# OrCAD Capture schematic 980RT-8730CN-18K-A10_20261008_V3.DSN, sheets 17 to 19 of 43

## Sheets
17 P0051_S5_DUT1: size Custom
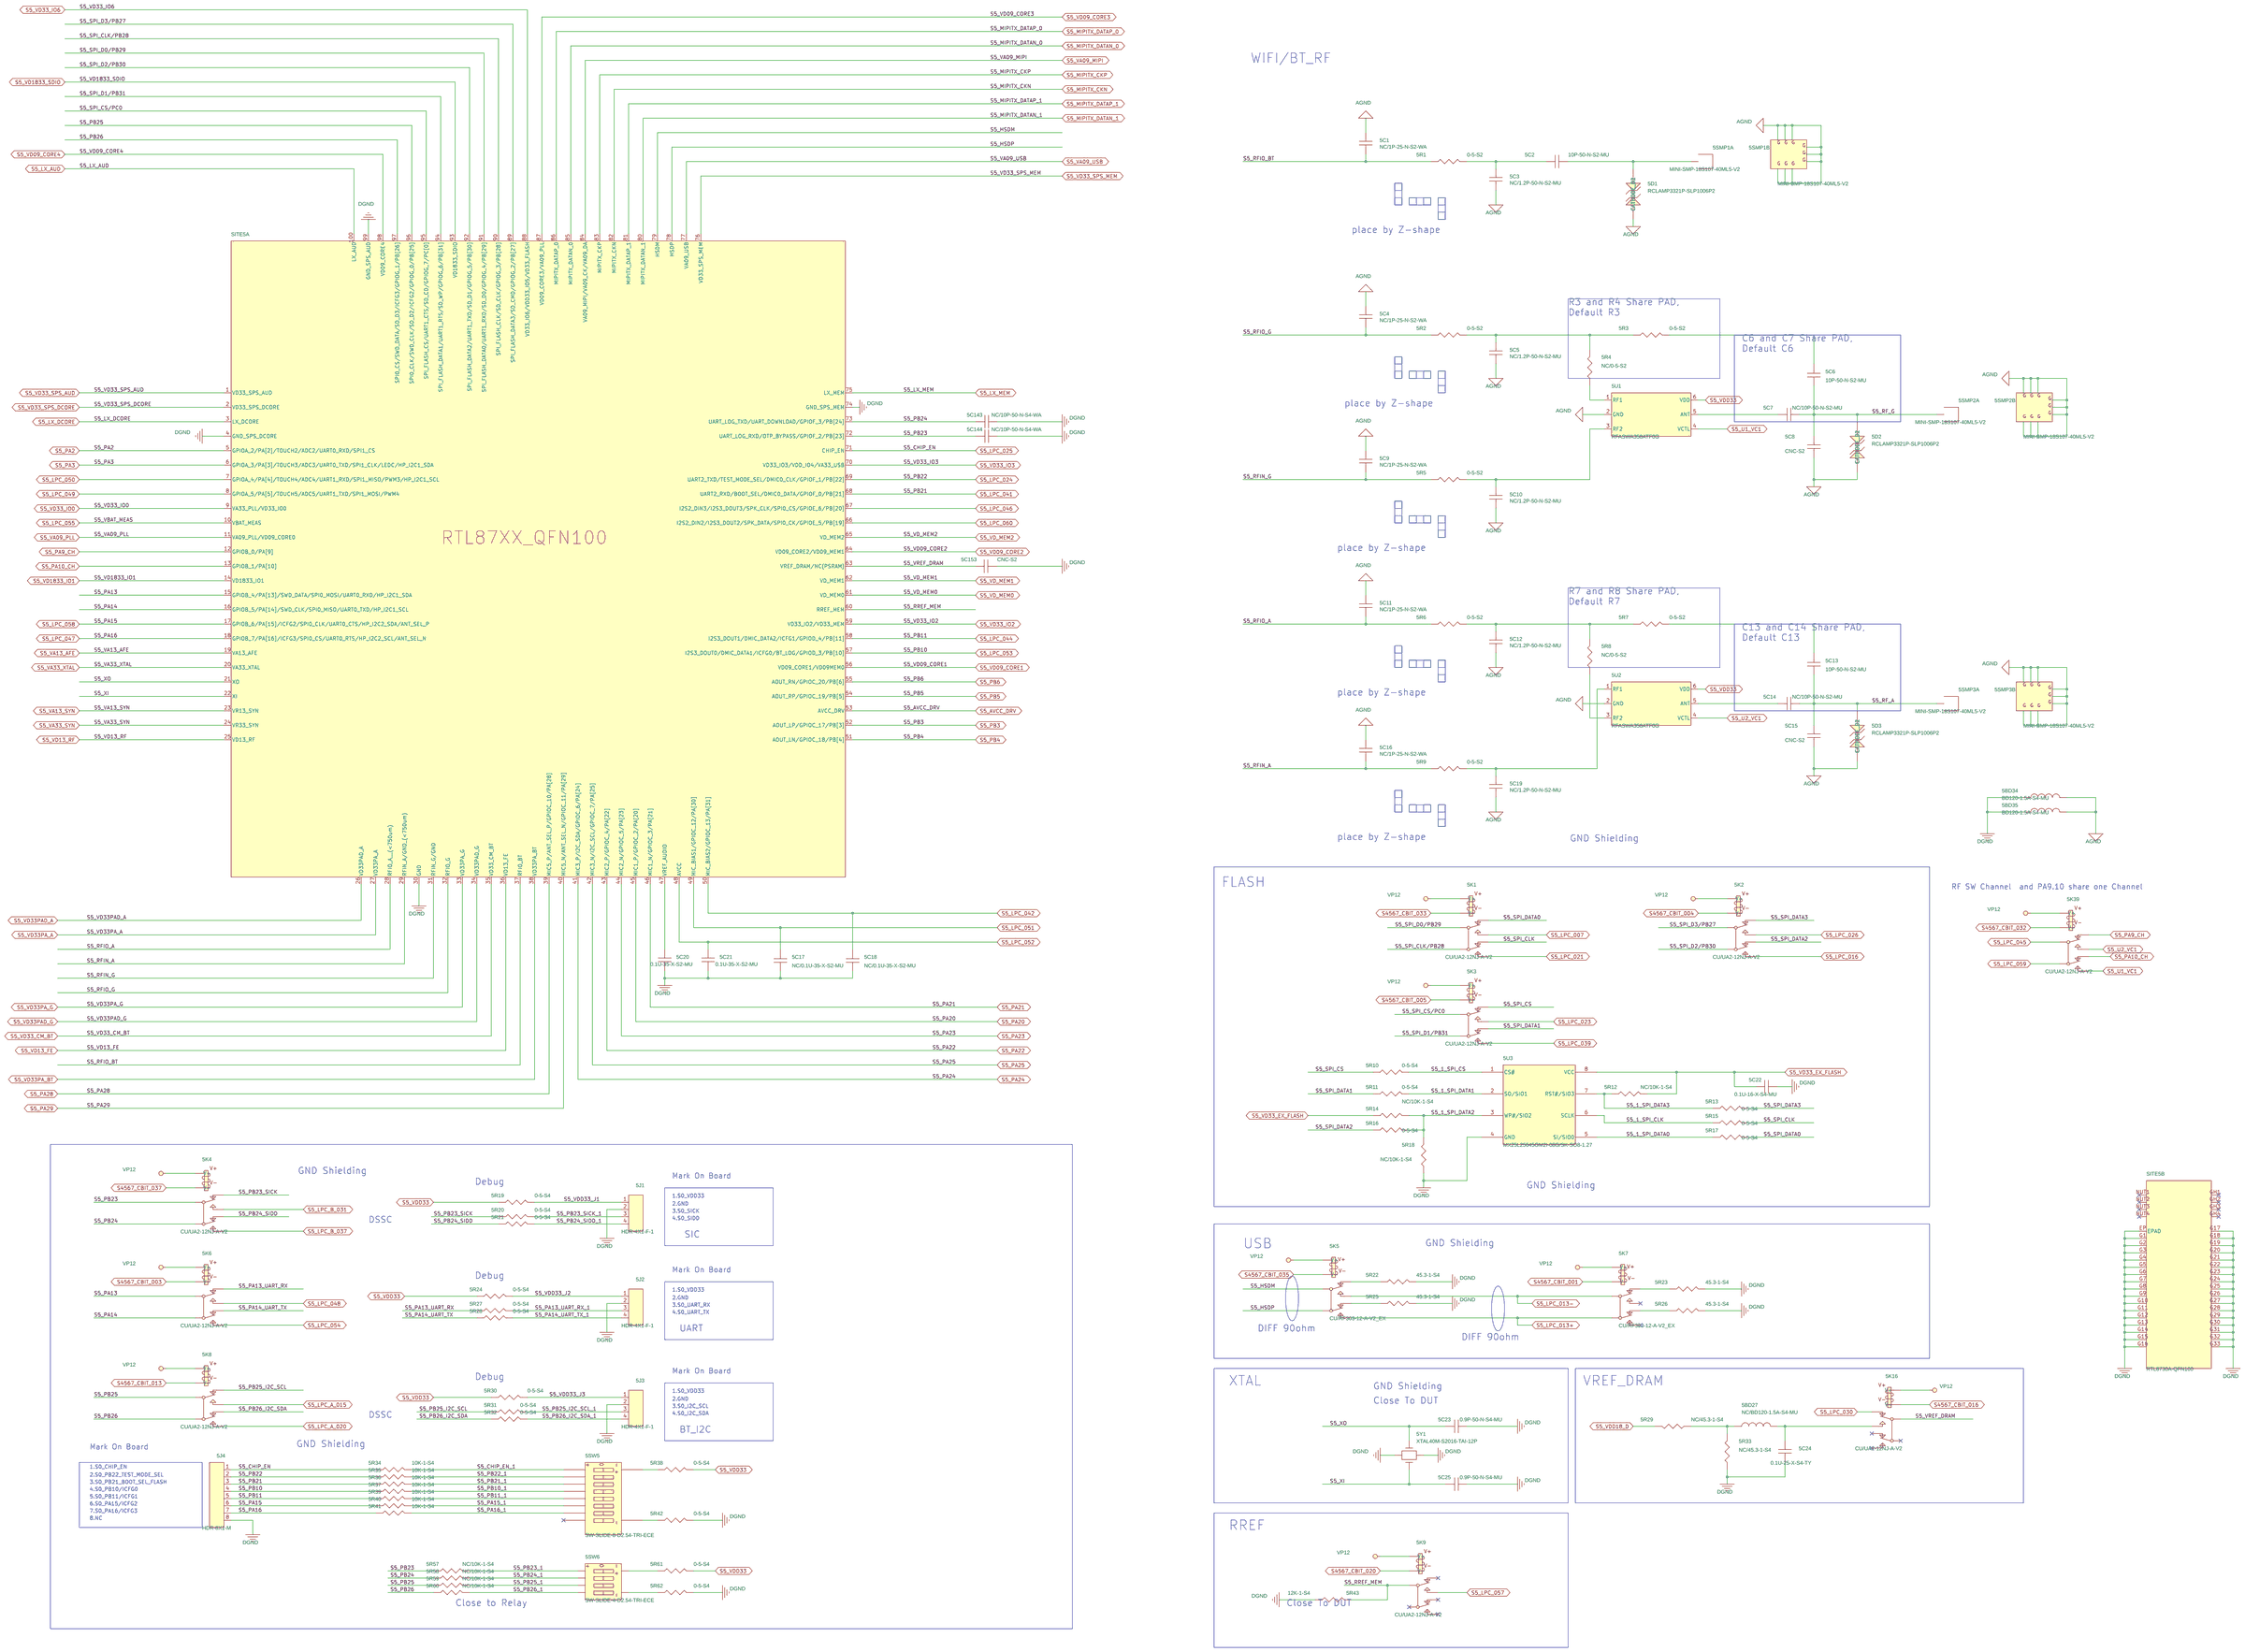
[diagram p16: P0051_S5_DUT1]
18 P0052_S5_Function-test: size A3
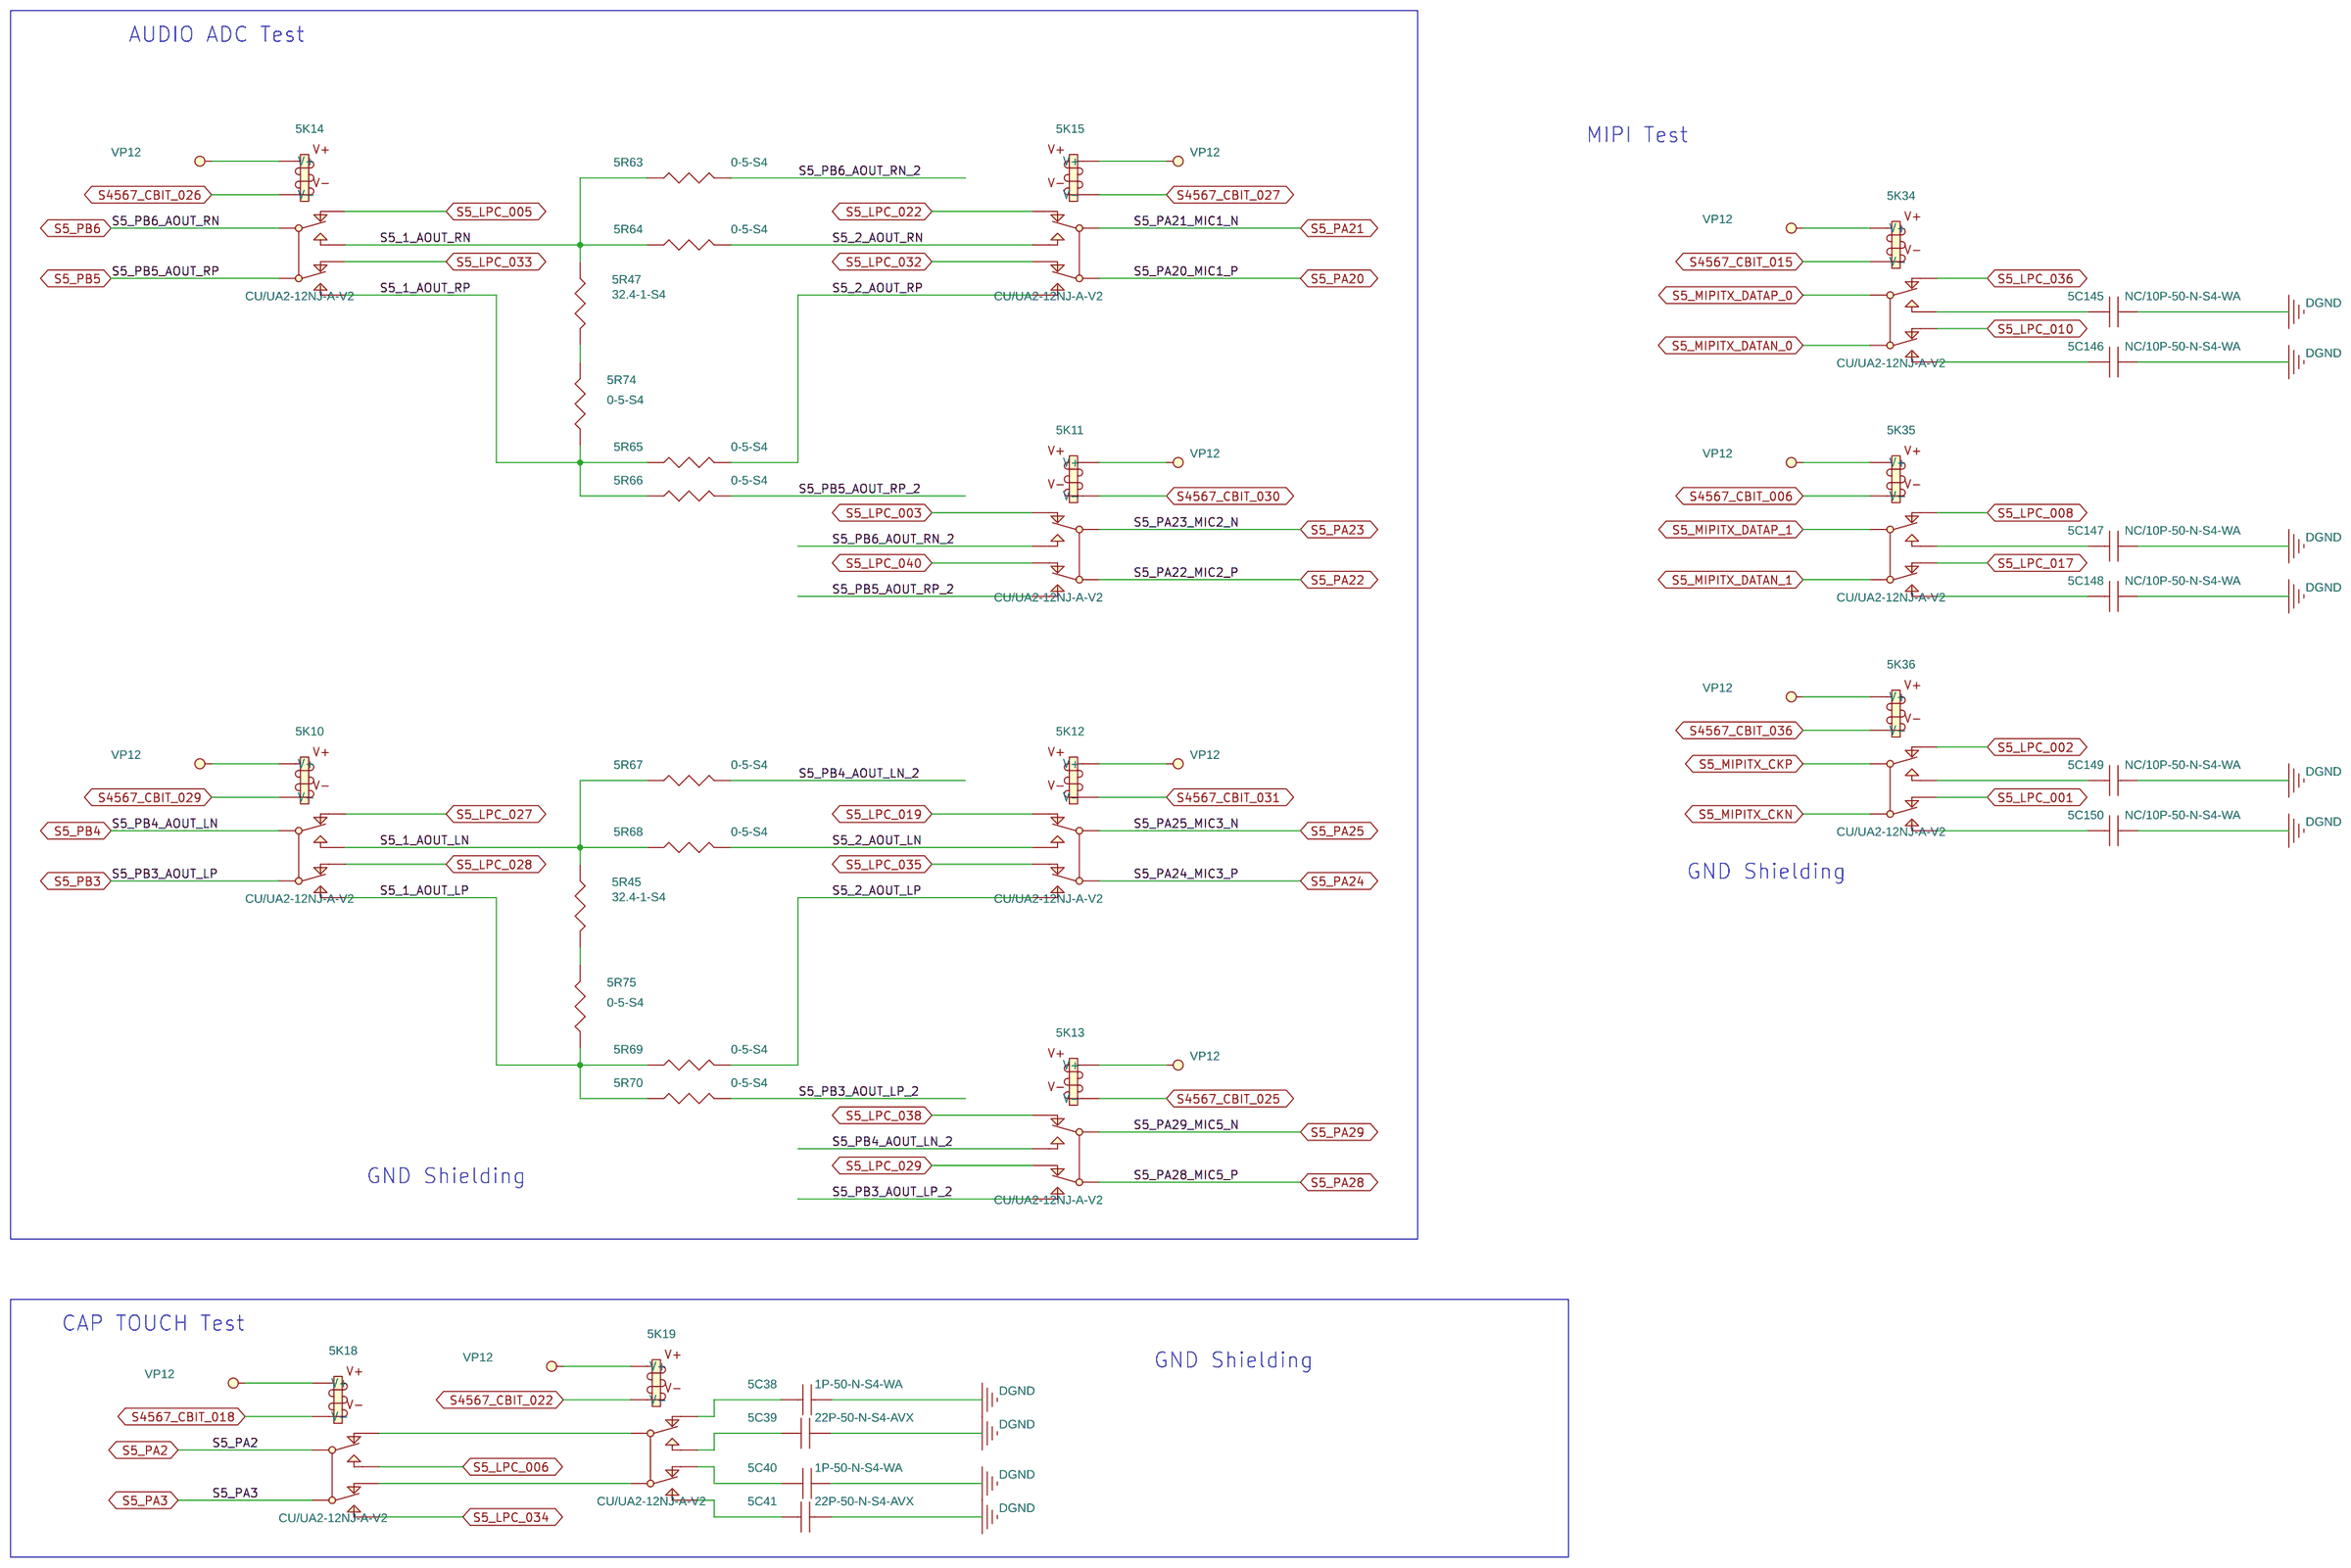
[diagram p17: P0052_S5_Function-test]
19 P0053_S5_Power: size A1
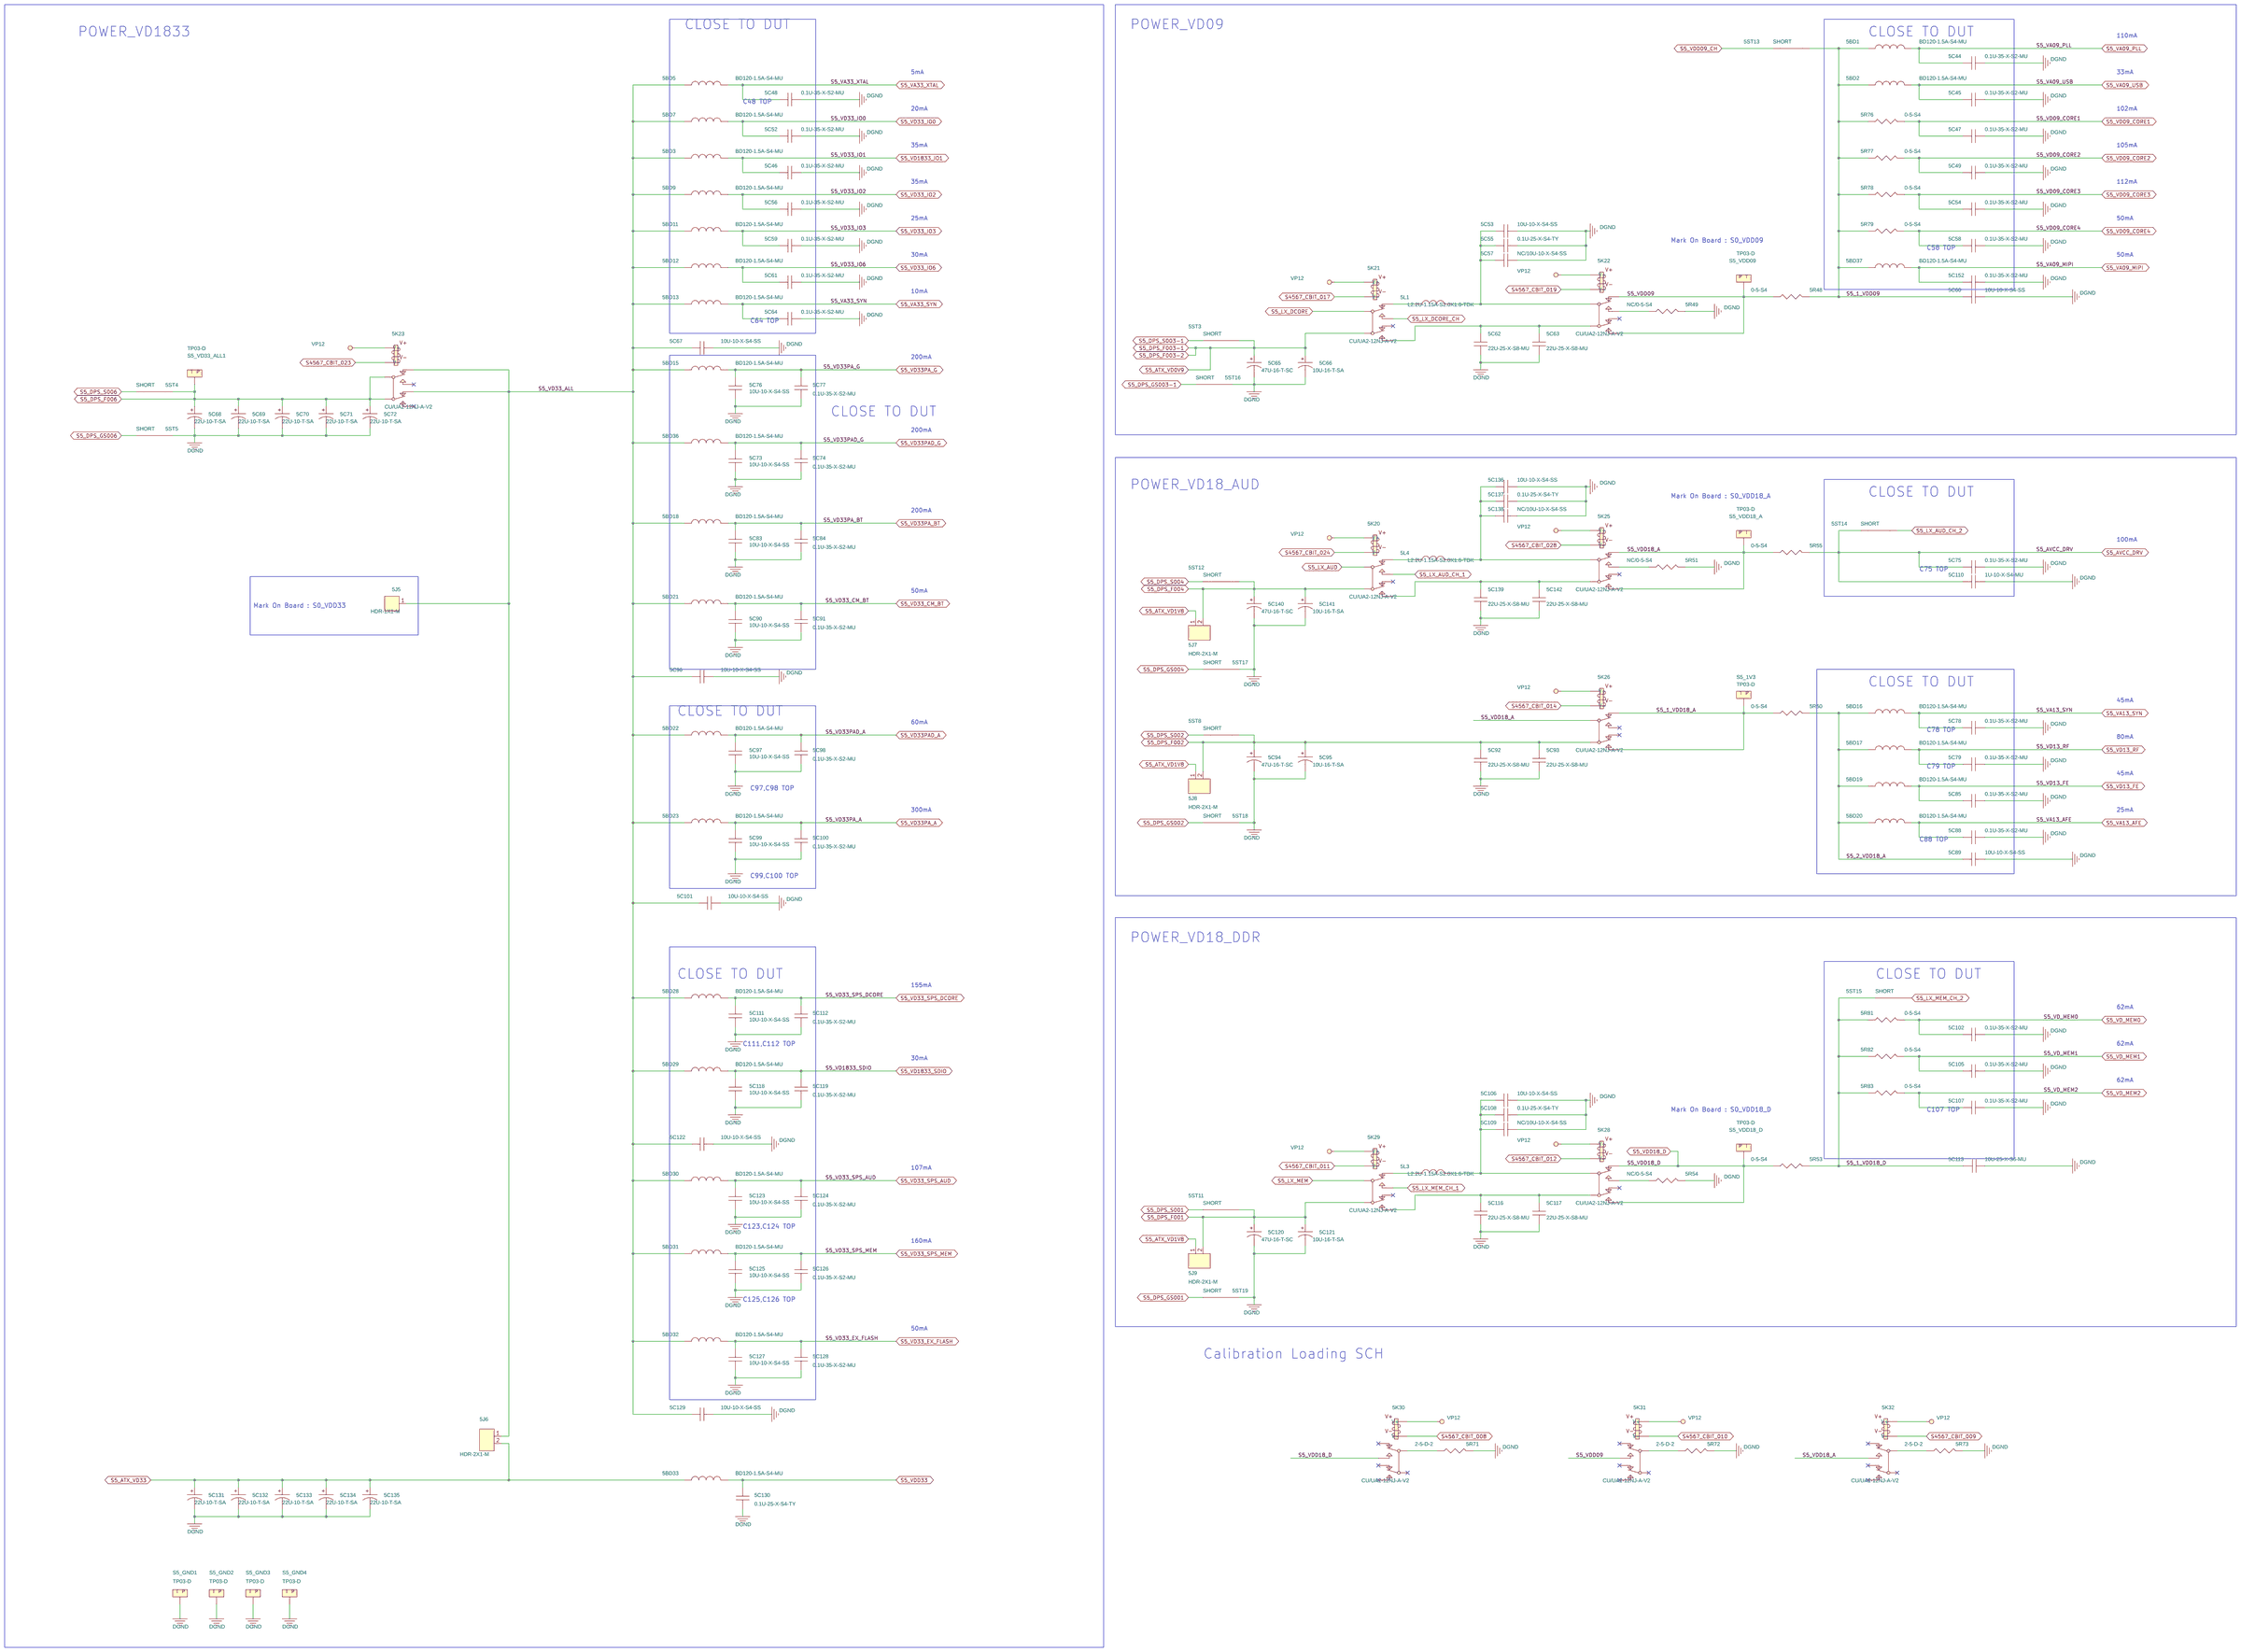
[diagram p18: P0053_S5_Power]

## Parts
sheet P0051_S5_DUT1
5BD27  NC/BD120-1.5A-S4-MU  [FB0402]
5BD34  BD120-1.5A-S4-MU  [FB0402]
5BD35  BD120-1.5A-S4-MU  [FB0402]
5C1  NC/1P-25-N-S2-WA  [C0201]
5C2  10P-50-N-S2-MU  [C0201]
5C3  NC/1.2P-50-N-S2-MU  [C0201]
5C4  NC/1P-25-N-S2-WA  [C0201]
5C5  NC/1.2P-50-N-S2-MU  [C0201]
5C6  10P-50-N-S2-MU  [C0201]
5C7  NC/10P-50-N-S2-MU  [C0201]
5C8  CNC-S2  [C0201]
5C9  NC/1P-25-N-S2-WA  [C0201]
5C10  NC/1.2P-50-N-S2-MU  [C0201]
5C11  NC/1P-25-N-S2-WA  [C0201]
5C12  NC/1.2P-50-N-S2-MU  [C0201]
5C13  10P-50-N-S2-MU  [C0201]
5C14  NC/10P-50-N-S2-MU  [C0201]
5C15  CNC-S2  [C0201]
5C16  NC/1P-25-N-S2-WA  [C0201]
5C17  NC/0.1U-35-X-S2-MU  [C0201]
5C18  NC/0.1U-35-X-S2-MU  [C0201]
5C19  NC/1.2P-50-N-S2-MU  [C0201]
5C20  0.1U-35-X-S2-MU  [C0201]
5C21  0.1U-35-X-S2-MU  [C0201]
5C22  0.1U-16-X-S4-MU  [C0402]
5C23  0.9P-50-N-S4-MU  [C0402]
5C24  0.1U-25-X-S4-TY  [C0402]
5C25  0.9P-50-N-S4-MU  [C0402]
5C143  NC/10P-50-N-S4-WA  [C0402]
5C144  NC/10P-50-N-S4-WA  [C0402]
5C153  CNC-S2  [C0201]
5D1  RCLAMP3321P-SLP1006P2  [DIODE_1X0P6MM]
5D2  RCLAMP3321P-SLP1006P2  [DIODE_1X0P6MM]
5D3  RCLAMP3321P-SLP1006P2  [DIODE_1X0P6MM]
5J1  HDR-4X1-F-1  [CONN_4X1_2P54MM_FL10P5MM]
5J2  HDR-4X1-F-1  [CONN_4X1_2P54MM_FL10P5MM]
5J3  HDR-4X1-F-1  [CONN_4X1_2P54MM_FL10P5MM]
5J4  HDR-8X1-M  [JP_8P_100]
5K1  CU/UA2-12NJ-A-V2  [RL_NECUA2_12V_V2]
5K2  CU/UA2-12NJ-A-V2  [RL_NECUA2_12V_V2]
5K3  CU/UA2-12NJ-A-V2  [RL_NECUA2_12V_V2]
5K4  CU/UA2-12NJ-A-V2  [RL_NECUA2_12V_V2]
5K5  CU/RF303-12-A-V2_EX  [RL_RF303_12V_V2]
5K6  CU/UA2-12NJ-A-V2  [RL_NECUA2_12V_V2]
5K7  CU/RF303-12-A-V2_EX  [RL_RF303_12V_V2]
5K8  CU/UA2-12NJ-A-V2  [RL_NECUA2_12V_V2]
5K9  CU/UA2-12NJ-A-V2  [RL_NECUA2_12V_V2]
5K16  CU/UA2-12NJ-A-V2  [RL_NECUA2_12V_V2]
5K39  CU/UA2-12NJ-A-V2  [RL_NECUA2_12V_V2]
5R1  0-5-S2  [R0201]
5R2  0-5-S2  [R0201]
5R3  0-5-S2  [R0201]
5R4  NC/0-5-S2  [R0201]
5R5  0-5-S2  [R0201]
5R6  0-5-S2  [R0201]
5R7  0-5-S2  [R0201]
5R8  NC/0-5-S2  [R0201]
5R9  0-5-S2  [R0201]
5R10  0-5-S4  [R0402]
5R11  0-5-S4  [R0402]
5R12  NC/10K-1-S4  [R0402]
5R13  0-5-S4  [R0402]
5R14  NC/10K-1-S4  [R0402]
5R15  0-5-S4  [R0402]
5R16  0-5-S4  [R0402]
5R17  0-5-S4  [R0402]
5R18  NC/10K-1-S4  [R0402]
5R19  0-5-S4  [R0402]
5R20  0-5-S4  [R0402]
5R21  0-5-S4  [R0402]
5R22  45.3-1-S4  [R0402]
5R23  45.3-1-S4  [R0402]
5R24  0-5-S4  [R0402]
5R25  45.3-1-S4  [R0402]
5R26  45.3-1-S4  [R0402]
5R27  0-5-S4  [R0402]
5R28  0-5-S4  [R0402]
5R29  NC/45.3-1-S4  [R0402]
5R30  0-5-S4  [R0402]
5R31  0-5-S4  [R0402]
5R32  0-5-S4  [R0402]
5R33  NC/45.3-1-S4  [R0402]
5R34  10K-1-S4  [R0402]
5R35  10K-1-S4  [R0402]
5R36  10K-1-S4  [R0402]
5R37  10K-1-S4  [R0402]
5R38  0-5-S4  [R0402]
5R39  10K-1-S4  [R0402]
5R40  10K-1-S4  [R0402]
5R41  10K-1-S4  [R0402]
5R42  0-5-S4  [R0402]
5R43  12K-1-S4  [R0402]
5R57  NC/10K-1-S4  [R0402]
5R58  NC/10K-1-S4  [R0402]
5R59  NC/10K-1-S4  [R0402]
5R60  NC/10K-1-S4  [R0402]
5R61  0-5-S4  [R0402]
5R62  0-5-S4  [R0402]
5SMP1  MINI-SMP-18S107-40ML5-V2  [CONN_SMP_18S107]  (sections A,B)
5SMP2  MINI-SMP-18S107-40ML5-V2  [CONN_SMP_18S107]  (sections A,B)
5SMP3  MINI-SMP-18S107-40ML5-V2  [CONN_SMP_18S107]  (sections A,B)
5SW5  SW-SLIDE-8-D2.54-TRI-ECE  [SW_DIPX8P_2P54_MM_V2]
5SW6  SW-SLIDE-4-D2.54-TRI-ECE  [SW_DIPX4P_2P54MM_ETD]
5U1  RFASWA358ATF0G  [RF_SW_GW2159_6P]
5U2  RFASWA358ATF0G  [RF_SW_GW2159_6P]
5U3  MX25L25645GM2I-08G/SK-SO8-1.27  [SK_SO8_1P27MM_LOTES]
5Y1  XTAL40M-S2016-TAI-12P  [XTAL_2X1P6MM_4P_0P8MM]
SITE5  RTL8730A-QFN100  [SK_QFN100P_0P35MM_MJC_L8730A]  (sections A,B)
sheet P0052_S5_Function-test
5C38  1P-50-N-S4-WA  [C0402]
5C39  22P-50-N-S4-AVX  [C0402]
5C40  1P-50-N-S4-WA  [C0402]
5C41  22P-50-N-S4-AVX  [C0402]
5C145  NC/10P-50-N-S4-WA  [C0402]
5C146  NC/10P-50-N-S4-WA  [C0402]
5C147  NC/10P-50-N-S4-WA  [C0402]
5C148  NC/10P-50-N-S4-WA  [C0402]
5C149  NC/10P-50-N-S4-WA  [C0402]
5C150  NC/10P-50-N-S4-WA  [C0402]
5K10  CU/UA2-12NJ-A-V2  [RL_NECUA2_12V_V2]
5K11  CU/UA2-12NJ-A-V2  [RL_NECUA2_12V_V2]
5K12  CU/UA2-12NJ-A-V2  [RL_NECUA2_12V_V2]
5K13  CU/UA2-12NJ-A-V2  [RL_NECUA2_12V_V2]
5K14  CU/UA2-12NJ-A-V2  [RL_NECUA2_12V_V2]
5K15  CU/UA2-12NJ-A-V2  [RL_NECUA2_12V_V2]
5K18  CU/UA2-12NJ-A-V2  [RL_NECUA2_12V_V2]
5K19  CU/UA2-12NJ-A-V2  [RL_NECUA2_12V_V2]
5K34  CU/UA2-12NJ-A-V2  [RL_NECUA2_12V_V2]
5K35  CU/UA2-12NJ-A-V2  [RL_NECUA2_12V_V2]
5K36  CU/UA2-12NJ-A-V2  [RL_NECUA2_12V_V2]
5R45  32.4-1-S4  [R0402]
5R47  32.4-1-S4  [R0402]
5R63  0-5-S4  [R0402]
5R64  0-5-S4  [R0402]
5R65  0-5-S4  [R0402]
5R66  0-5-S4  [R0402]
5R67  0-5-S4  [R0402]
5R68  0-5-S4  [R0402]
5R69  0-5-S4  [R0402]
5R70  0-5-S4  [R0402]
5R74  0-5-S4  [R0402]
5R75  0-5-S4  [R0402]
sheet P0053_S5_Power
5BD1  BD120-1.5A-S4-MU  [FB0402]
5BD2  BD120-1.5A-S4-MU  [FB0402]
5BD3  BD120-1.5A-S4-MU  [FB0402]
5BD5  BD120-1.5A-S4-MU  [FB0402]
5BD7  BD120-1.5A-S4-MU  [FB0402]
5BD9  BD120-1.5A-S4-MU  [FB0402]
5BD11  BD120-1.5A-S4-MU  [FB0402]
5BD12  BD120-1.5A-S4-MU  [FB0402]
5BD13  BD120-1.5A-S4-MU  [FB0402]
5BD15  BD120-1.5A-S4-MU  [FB0402]
5BD16  BD120-1.5A-S4-MU  [FB0402]
5BD17  BD120-1.5A-S4-MU  [FB0402]
5BD18  BD120-1.5A-S4-MU  [FB0402]
5BD19  BD120-1.5A-S4-MU  [FB0402]
5BD20  BD120-1.5A-S4-MU  [FB0402]
5BD21  BD120-1.5A-S4-MU  [FB0402]
5BD22  BD120-1.5A-S4-MU  [FB0402]
5BD23  BD120-1.5A-S4-MU  [FB0402]
5BD28  BD120-1.5A-S4-MU  [FB0402]
5BD29  BD120-1.5A-S4-MU  [FB0402]
5BD30  BD120-1.5A-S4-MU  [FB0402]
5BD31  BD120-1.5A-S4-MU  [FB0402]
5BD32  BD120-1.5A-S4-MU  [FB0402]
5BD33  BD120-1.5A-S4-MU  [FB0402]
5BD36  BD120-1.5A-S4-MU  [FB0402]
5BD37  BD120-1.5A-S4-MU  [FB0402]
5C44  0.1U-35-X-S2-MU  [C0201]
5C45  0.1U-35-X-S2-MU  [C0201]
5C46  0.1U-35-X-S2-MU  [C0201]
5C47  0.1U-35-X-S2-MU  [C0201]
5C48  0.1U-35-X-S2-MU  [C0201]
5C49  0.1U-35-X-S2-MU  [C0201]
5C52  0.1U-35-X-S2-MU  [C0201]
5C53  10U-10-X-S4-SS  [C0402]
5C54  0.1U-35-X-S2-MU  [C0201]
5C55  0.1U-25-X-S4-TY  [C0402]
5C56  0.1U-35-X-S2-MU  [C0201]
5C57  NC/10U-10-X-S4-SS  [C0402]
5C58  0.1U-35-X-S2-MU  [C0201]
5C59  0.1U-35-X-S2-MU  [C0201]
5C60  10U-10-X-S4-SS  [C0402]
5C61  0.1U-35-X-S2-MU  [C0201]
5C62  22U-25-X-S8-MU  [C0805]
5C63  22U-25-X-S8-MU  [C0805]
5C64  0.1U-35-X-S2-MU  [C0201]
5C65  47U-16-T-SC  [CODE_C]
5C66  10U-16-T-SA  [CODE_A]
5C67  10U-10-X-S4-SS  [C0402]
5C68  22U-10-T-SA  [CODE_A]
5C69  22U-10-T-SA  [CODE_A]
5C70  22U-10-T-SA  [CODE_A]
5C71  22U-10-T-SA  [CODE_A]
5C72  22U-10-T-SA  [CODE_A]
5C73  10U-10-X-S4-SS  [C0402]
5C74  0.1U-35-X-S2-MU  [C0201]
5C75  0.1U-35-X-S2-MU  [C0201]
5C76  10U-10-X-S4-SS  [C0402]
5C77  0.1U-35-X-S2-MU  [C0201]
5C78  0.1U-35-X-S2-MU  [C0201]
5C79  0.1U-35-X-S2-MU  [C0201]
5C83  10U-10-X-S4-SS  [C0402]
5C84  0.1U-35-X-S2-MU  [C0201]
5C85  0.1U-35-X-S2-MU  [C0201]
5C88  0.1U-35-X-S2-MU  [C0201]
5C89  10U-10-X-S4-SS  [C0402]
5C90  10U-10-X-S4-SS  [C0402]
5C91  0.1U-35-X-S2-MU  [C0201]
5C92  22U-25-X-S8-MU  [C0805]
5C93  22U-25-X-S8-MU  [C0805]
5C94  47U-16-T-SC  [CODE_C]
5C95  10U-16-T-SA  [CODE_A]
5C96  10U-10-X-S4-SS  [C0402]
5C97  10U-10-X-S4-SS  [C0402]
5C98  0.1U-35-X-S2-MU  [C0201]
5C99  10U-10-X-S4-SS  [C0402]
5C100  0.1U-35-X-S2-MU  [C0201]
5C101  10U-10-X-S4-SS  [C0402]
5C102  0.1U-35-X-S2-MU  [C0201]
5C105  0.1U-35-X-S2-MU  [C0201]
5C106  10U-10-X-S4-SS  [C0402]
5C107  0.1U-35-X-S2-MU  [C0201]
5C108  0.1U-25-X-S4-TY  [C0402]
5C109  NC/10U-10-X-S4-SS  [C0402]
5C110  1U-10-X-S4-MU  [C0402]
5C111  10U-10-X-S4-SS  [C0402]
5C112  0.1U-35-X-S2-MU  [C0201]
5C113  10U-25-X-S6-MU  [C0603]
5C116  22U-25-X-S8-MU  [C0805]
5C117  22U-25-X-S8-MU  [C0805]
5C118  10U-10-X-S4-SS  [C0402]
5C119  0.1U-35-X-S2-MU  [C0201]
5C120  47U-16-T-SC  [CODE_C]
5C121  10U-16-T-SA  [CODE_A]
5C122  10U-10-X-S4-SS  [C0402]
5C123  10U-10-X-S4-SS  [C0402]
5C124  0.1U-35-X-S2-MU  [C0201]
5C125  10U-10-X-S4-SS  [C0402]
5C126  0.1U-35-X-S2-MU  [C0201]
5C127  10U-10-X-S4-SS  [C0402]
5C128  0.1U-35-X-S2-MU  [C0201]
5C129  10U-10-X-S4-SS  [C0402]
5C130  0.1U-25-X-S4-TY  [C0402]
5C131  22U-10-T-SA  [CODE_A]
5C132  22U-10-T-SA  [CODE_A]
5C133  22U-10-T-SA  [CODE_A]
5C134  22U-10-T-SA  [CODE_A]
5C135  22U-10-T-SA  [CODE_A]
5C136  10U-10-X-S4-SS  [C0402]
5C137  0.1U-25-X-S4-TY  [C0402]
5C138  NC/10U-10-X-S4-SS  [C0402]
5C139  22U-25-X-S8-MU  [C0805]
5C140  47U-16-T-SC  [CODE_C]
5C141  10U-16-T-SA  [CODE_A]
5C142  22U-25-X-S8-MU  [C0805]
5C152  0.1U-35-X-S2-MU  [C0201]
5J5  HDR-1X1-M  [JP_1P_RD070_040]
5J6  HDR-2X1-M  [JP_2P_100]
5J7  HDR-2X1-M  [JP_2P_100]
5J8  HDR-2X1-M  [JP_2P_100]
5J9  HDR-2X1-M  [JP_2P_100]
5K20  CU/UA2-12NJ-A-V2  [RL_NECUA2_12V_V2]
5K21  CU/UA2-12NJ-A-V2  [RL_NECUA2_12V_V2]
5K22  CU/UA2-12NJ-A-V2  [RL_NECUA2_12V_V2]
5K23  CU/UA2-12NJ-A-V2  [RL_NECUA2_12V_V2]
5K25  CU/UA2-12NJ-A-V2  [RL_NECUA2_12V_V2]
5K26  CU/UA2-12NJ-A-V2  [RL_NECUA2_12V_V2]
5K28  CU/UA2-12NJ-A-V2  [RL_NECUA2_12V_V2]
5K29  CU/UA2-12NJ-A-V2  [RL_NECUA2_12V_V2]
5K30  CU/UA2-12NJ-A-V2  [RL_NECUA2_12V_V2]
5K31  CU/UA2-12NJ-A-V2  [RL_NECUA2_12V_V2]
5K32  CU/UA2-12NJ-A-V2  [RL_NECUA2_12V_V2]
5L1  L2.2U-1.15A-S2.0X1.6-TDK  [IND_VL252012E]
5L3  L2.2U-1.15A-S2.0X1.6-TDK  [IND_VL252012E]
5L4  L2.2U-1.15A-S2.0X1.6-TDK  [IND_VL252012E]
5R48  0-5-S4  [R0402]
5R49  NC/0-5-S4  [R0402]
5R50  0-5-S4  [R0402]
5R51  NC/0-5-S4  [R0402]
5R53  0-5-S4  [R0402]
5R54  NC/0-5-S4  [R0402]
5R55  0-5-S4  [R0402]
5R71  2-5-D-2  [RC02W_27MM]
5R72  2-5-D-2  [RC02W_27MM]
5R73  2-5-D-2  [RC02W_27MM]
5R76  0-5-S4  [R0402]
5R77  0-5-S4  [R0402]
5R78  0-5-S4  [R0402]
5R79  0-5-S4  [R0402]
5R81  0-5-S4  [R0402]
5R82  0-5-S4  [R0402]
5R83  0-5-S4  [R0402]
5ST3  SHORT  [DEFAULT_SHORT_SMALL]
5ST4  SHORT  [DEFAULT_SHORT_SMALL]
5ST5  SHORT  [DEFAULT_SHORT_SMALL]
5ST8  SHORT  [DEFAULT_SHORT_SMALL]
5ST11  SHORT  [DEFAULT_SHORT_SMALL]
5ST12  SHORT  [DEFAULT_SHORT_SMALL]
5ST13  SHORT  [DEFAULT_SHORT_SMALL]
5ST14  SHORT  [DEFAULT_SHORT_SMALL]
5ST15  SHORT  [DEFAULT_SHORT_SMALL]
5ST16  SHORT  [DEFAULT_SHORT_SMALL]
5ST17  SHORT  [DEFAULT_SHORT_SMALL]
5ST18  SHORT  [DEFAULT_SHORT_SMALL]
5ST19  SHORT  [DEFAULT_SHORT_SMALL]
S5_1V3  TP03-D  [TP_060_040]
S5_GND1  TP03-D  [TP_060_040]
S5_GND2  TP03-D  [TP_060_040]
S5_GND3  TP03-D  [TP_060_040]
S5_GND4  TP03-D  [TP_060_040]
S5_VD33_ALL1  TP03-D  [TP_060_040]
S5_VDD09  TP03-D  [TP_060_040]
S5_VDD18_A  TP03-D  [TP_060_040]
S5_VDD18_D  TP03-D  [TP_060_040]

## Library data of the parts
5BD27 = BD120-1.5A-S4-MU: KAIROSNAME: BD27
5BD34 = BD120-1.5A-S4-MU: KAIROSNAME: BD34
5BD35 = BD120-1.5A-S4-MU: KAIROSNAME: BD35
5C1 5C4 5C9 5C11 5C16 = 1P-25-N-S2-WA
5C2 5C6 5C7 5C13 5C14 = 10P-50-N-S2-MU
5C3 5C5 5C10 5C12 5C19 = 1.2P-50-N-S2-MU
5C8 5C15 = CNC-S4
5C17 5C18 5C46 = 0.1U-35-X-S2-MU: KAIROSNAME: C46
5C20 5C21 5C98 = 0.1U-35-X-S2-MU: KAIROSNAME: C98
5C22 = 0.1U-16-X-S4: KAIROSNAME: C22
5C23 = 10P-50-N-S4-MU-1: KAIROSNAME: C23
5C24 = 0.1U-25-X-S4-TY: KAIROSNAME: C24
5C25 = 10P-50-N-S4-MU-1: KAIROSNAME: C25
5C143-5C150 = 10P-50-N-S4-WA
5C48 5C153 = 0.1U-35-X-S2-MU: KAIROSNAME: C48
5D1 = RCLAMP3321P-SLP1006P2: KAIROSNAME: D1
5D2 = RCLAMP3321P-SLP1006P2: KAIROSNAME: D2
5D3 = RCLAMP3321P-SLP1006P2: KAIROSNAME: D3
5J1-5J3 = HDR-4X1-F-1
5J4 = HDR-8X1-M: KAIROSNAME: J4
5K1 5K39 = CU_UA2-12NJ-A-V2: KAIROSNAME: K1
5K2 5K16 = CU_UA2-12NJ-A-V2: KAIROSNAME: K2
5K3 = CU_UA2-12NJ-A-V2: KAIROSNAME: K3
5K4 = CU_UA2-12NJ-A-V2: KAIROSNAME: K4
5K5 = CU_RF303-12-A-V2_EX: KAIROSNAME: K5
5K6 = CU_UA2-12NJ-A-V2: KAIROSNAME: K6
5K7 = CU_RF303-12-A-V2_EX: KAIROSNAME: K7
5K8 = CU_UA2-12NJ-A-V2: KAIROSNAME: K8
5K9 = CU_UA2-12NJ-A-V2: KAIROSNAME: K9
5R1-5R9 = 0-5-S2
5R10 = 0-5-S4: KAIROSNAME: R10
5R11 = 0-5-S4: KAIROSNAME: R11
5R12 = 10K-1-S4: KAIROSNAME: R12
5R13 = 0-5-S4: KAIROSNAME: R13
5R14 = 10K-1-S4: KAIROSNAME: R14
5R15 = 0-5-S4: KAIROSNAME: R15
5R16 = 0-5-S4: KAIROSNAME: R16
5R17 = 0-5-S4: KAIROSNAME: R17
5R18 = 10K-1-S4: KAIROSNAME: R18
5R19 = 0-5-S4: KAIROSNAME: R19
5R20 = 0-5-S4: KAIROSNAME: R20
5R21 = 0-5-S4: KAIROSNAME: R21
5R22 = 45.3-1-S4: KAIROSNAME: R22
5R23 = 45.3-1-S4: KAIROSNAME: R23
5R24 = 0-5-S4: KAIROSNAME: R24
5R25 = 45.3-1-S4: KAIROSNAME: R25
5R26 = 45.3-1-S4: KAIROSNAME: R26
5R27 = 0-5-S4: KAIROSNAME: R27
5R28 = 0-5-S4: KAIROSNAME: R28
5R29 = 45.3-1-S4: KAIROSNAME: R29
5R30 = 0-5-S4: KAIROSNAME: R30
5R31 = 0-5-S4: KAIROSNAME: R31
5R32 = 0-5-S4: KAIROSNAME: R32
5R33 = 45.3-1-S4: KAIROSNAME: R33
5R34 = 10K-1-S4: KAIROSNAME: R34
5R35 = 10K-1-S4: KAIROSNAME: R35
5R36 = 10K-1-S4: KAIROSNAME: R36
5R37 = 10K-1-S4: KAIROSNAME: R37
5R38 = 0-5-S4: KAIROSNAME: R38
5R39 = 10K-1-S4: KAIROSNAME: R39
5R40 = 10K-1-S4: KAIROSNAME: R40
5R41 = 10K-1-S4: KAIROSNAME: R41
5R42 = 0-5-S4: KAIROSNAME: R42
5R43 = 12K-1-S4: KAIROSNAME: R43
5R57 = 10K-1-S4: KAIROSNAME: R57
5R58 = 10K-1-S4: KAIROSNAME: R58
5R59 = 10K-1-S4: KAIROSNAME: R59
5R60 = 10K-1-S4: KAIROSNAME: R60
5R61 = 0-5-S4: KAIROSNAME: R61
5R62 = 0-5-S4: KAIROSNAME: R62
5SMP1 = MINI-SMP-18S107-40ML5-V2: KAIROSNAME: SMP1A
5SMP2 = MINI-SMP-18S107-40ML5-V2: KAIROSNAME: SMP2A
5SMP3 = MINI-SMP-18S107-40ML5-V2: KAIROSNAME: SMP3B
5SW5 = SW-SLIDE-8-D2.54-TRI-ECE
5SW6 = SW-SLIDE-4-D2.54-TRI-ECE
5U1 5U2 = RFASWA358ATF0G
5U3 = MX25R6435FM2IL0-SOP8: KAIROSNAME: U3
5Y1 = XTAL40M-S2016-TAI-12P: KAIROSNAME: Y1
SITE5 = RTL8730A-QFN100
5C38 = 10P-50-N-S4-MU-1: KAIROSNAME: C38
5C39 = 33P-50-N-S4-WA: KAIROSNAME: C39
5C40 = 10P-50-N-S4-MU-1: KAIROSNAME: C40
5C41 = 33P-50-N-S4-WA: KAIROSNAME: C41
5K10 = CU_UA2-12NJ-A-V2: KAIROSNAME: K10
5K11 = CU_UA2-12NJ-A-V2: KAIROSNAME: K11
5K12 = CU_UA2-12NJ-A-V2: KAIROSNAME: K12
5K13 = CU_UA2-12NJ-A-V2: KAIROSNAME: K13
5K14 = CU_UA2-12NJ-A-V2: KAIROSNAME: K14
5K15 5K34-5K36 = CU_UA2-12NJ-A-V2: KAIROSNAME: K15
5K18 = CU_UA2-12NJ-A-V2: KAIROSNAME: K18
5K19 = CU_UA2-12NJ-A-V2: KAIROSNAME: K19
5R45 = 32.4-1-S4: KAIROSNAME: R45
5R47 = 32.4-1-S4: KAIROSNAME: R47
5R63 = 0-5-S4: KAIROSNAME: R63
5R64 = 0-5-S4: KAIROSNAME: R64
5R65 5R74 5R75 = 0-5-S4: KAIROSNAME: R65
5R66 = 0-5-S4: KAIROSNAME: R66
5R67 = 0-5-S4: KAIROSNAME: R67
5R68 = 0-5-S4: KAIROSNAME: R68
5R69 = 0-5-S4: KAIROSNAME: R69
5R70 = 0-5-S4: KAIROSNAME: R70
5BD1 = BD120-1.5A-S4-MU: KAIROSNAME: BD1
5BD2 = BD120-1.5A-S4-MU: KAIROSNAME: BD2
5BD3 = BD120-1.5A-S4-MU: KAIROSNAME: BD3
5BD5 = BD120-1.5A-S4-MU: KAIROSNAME: BD5
5BD7 = BD120-1.5A-S4-MU: KAIROSNAME: BD7
5BD9 = BD120-1.5A-S4-MU: KAIROSNAME: BD9
5BD11 = BD120-1.5A-S4-MU: KAIROSNAME: BD11
5BD12 = BD120-1.5A-S4-MU: KAIROSNAME: BD12
5BD13 = BD120-1.5A-S4-MU: KAIROSNAME: BD13
5BD15 5BD36 = BD120-1.5A-S4-MU: KAIROSNAME: BD15
5BD16 = BD120-1.5A-S4-MU: KAIROSNAME: BD16
5BD17 = BD120-1.5A-S4-MU: KAIROSNAME: BD17
5BD18 = BD120-1.5A-S4-MU: KAIROSNAME: BD18
5BD19 = BD120-1.5A-S4-MU: KAIROSNAME: BD19
5BD20 = BD120-1.5A-S4-MU: KAIROSNAME: BD20
5BD21 = BD120-1.5A-S4-MU: KAIROSNAME: BD21
5BD22 = BD120-1.5A-S4-MU: KAIROSNAME: BD22
5BD23 = BD120-1.5A-S4-MU: KAIROSNAME: BD23
5BD28 = BD120-1.5A-S4-MU: KAIROSNAME: BD28
5BD29 = BD120-1.5A-S4-MU: KAIROSNAME: BD29
5BD30 = BD120-1.5A-S4-MU: KAIROSNAME: BD30
5BD31 = BD120-1.5A-S4-MU: KAIROSNAME: BD31
5BD32 = BD120-1.5A-S4-MU: KAIROSNAME: BD32
5BD33 = BD120-1.5A-S4-MU: KAIROSNAME: BD33
5BD37 = BD120-1.5A-S4-MU: KAIROSNAME: BD10
5C44 = 0.1U-35-X-S2-MU: KAIROSNAME: C44
5C45 = 0.1U-35-X-S2-MU: KAIROSNAME: C45
5C47 = 0.1U-35-X-S2-MU: KAIROSNAME: C47
5C49 = 0.1U-35-X-S2-MU: KAIROSNAME: C49
5C52 = 0.1U-35-X-S2-MU: KAIROSNAME: C52
5C53 = 10U-10-X-S4-SS: KAIROSNAME: C53
5C54 = 0.1U-35-X-S2-MU: KAIROSNAME: C54
5C55 = 0.1U-25-X-S4-TY: KAIROSNAME: C55
5C56 = 0.1U-35-X-S2-MU: KAIROSNAME: C56
5C57 = 10U-10-X-S4-SS: KAIROSNAME: C57
5C58 5C152 = 0.1U-35-X-S2-MU: KAIROSNAME: C58
5C59 = 0.1U-35-X-S2-MU: KAIROSNAME: C59
5C60 = 10U-10-X-S4-SS: KAIROSNAME: C60
5C61 = 0.1U-35-X-S2-MU: KAIROSNAME: C61
5C62 = 22U-25-X-S8-MU: KAIROSNAME: C62
5C63 = 22U-25-X-S8-MU: KAIROSNAME: C63
5C64 = 0.1U-35-X-S2-MU: KAIROSNAME: C64
5C65 = 47U-16-T-SC: KAIROSNAME: C65
5C66 = 10U-16-T-SA: KAIROSNAME: C66
5C67 = 10U-10-X-S4-SS: KAIROSNAME: C67
5C68 = 22U-10-T-SA: KAIROSNAME: C68
5C69 = 22U-10-T-SA: KAIROSNAME: C69
5C70 = 22U-10-T-SA: KAIROSNAME: C70
5C71 = 22U-10-T-SA: KAIROSNAME: C71
5C72 = 22U-10-T-SA: KAIROSNAME: C72
5C73 5C76 = 10U-10-X-S4-SS: KAIROSNAME: C76
5C74 5C77 = 0.1U-35-X-S2-MU: KAIROSNAME: C77
5C75 = 0.1U-35-X-S2-MU: KAIROSNAME: C75
5C78 = 0.1U-35-X-S2-MU: KAIROSNAME: C78
5C79 = 0.1U-35-X-S2-MU: KAIROSNAME: C79
5C83 = 10U-10-X-S4-SS: KAIROSNAME: C83
5C84 = 0.1U-35-X-S2-MU: KAIROSNAME: C84
5C85 = 0.1U-35-X-S2-MU: KAIROSNAME: C85
5C88 = 0.1U-35-X-S2-MU: KAIROSNAME: C88
5C89 = 10U-10-X-S4-SS: KAIROSNAME: C89
5C90 = 10U-10-X-S4-SS: KAIROSNAME: C90
5C91 = 0.1U-35-X-S2-MU: KAIROSNAME: C91
5C92 = 22U-25-X-S8-MU: KAIROSNAME: C92
5C93 = 22U-25-X-S8-MU: KAIROSNAME: C93
5C94 = 47U-16-T-SC: KAIROSNAME: C94
5C95 = 10U-16-T-SA: KAIROSNAME: C95
5C96 = 10U-10-X-S4-SS: KAIROSNAME: C96
5C97 = 10U-10-X-S4-SS: KAIROSNAME: C97
5C99 = 10U-10-X-S4-SS: KAIROSNAME: C99
5C100 = 0.1U-35-X-S2-MU: KAIROSNAME: C100
5C101 = 10U-10-X-S4-SS: KAIROSNAME: C101
5C102 = 0.1U-35-X-S2-MU: KAIROSNAME: C102
5C105 = 0.1U-35-X-S2-MU: KAIROSNAME: C105
5C106 = 10U-10-X-S4-SS: KAIROSNAME: C106
5C107 = 0.1U-35-X-S2-MU: KAIROSNAME: C107
5C108 = 0.1U-25-X-S4-TY: KAIROSNAME: C108
5C109 = 10U-10-X-S4-SS: KAIROSNAME: C109
5C110 = 10U-10-X-S4-SS: KAIROSNAME: C110
5C111 = 10U-10-X-S4-SS: KAIROSNAME: C111
5C112 = 0.1U-35-X-S2-MU: KAIROSNAME: C112
5C113 = 10U-25-X-S6-MU: KAIROSNAME: C113
5C116 = 22U-25-X-S8-MU: KAIROSNAME: C116
5C117 = 22U-25-X-S8-MU: KAIROSNAME: C117
5C118 = 10U-10-X-S4-SS: KAIROSNAME: C118
5C119 = 0.1U-35-X-S2-MU: KAIROSNAME: C119
5C120 = 47U-16-T-SC: KAIROSNAME: C120
5C121 = 10U-16-T-SA: KAIROSNAME: C121
5C122 = 10U-10-X-S4-SS: KAIROSNAME: C122
5C123 = 10U-10-X-S4-SS: KAIROSNAME: C123
5C124 = 0.1U-35-X-S2-MU: KAIROSNAME: C124
5C125 = 10U-10-X-S4-SS: KAIROSNAME: C125
5C126 = 0.1U-35-X-S2-MU: KAIROSNAME: C126
5C127 = 10U-10-X-S4-SS: KAIROSNAME: C127
5C128 = 0.1U-35-X-S2-MU: KAIROSNAME: C128
5C129 = 10U-10-X-S4-SS: KAIROSNAME: C129
5C130 = 0.1U-25-X-S4-TY: KAIROSNAME: C130
5C131 = 22U-10-T-SA: KAIROSNAME: C131
5C132 = 22U-10-T-SA: KAIROSNAME: C132
5C133 = 22U-10-T-SA: KAIROSNAME: C133
5C134 = 22U-10-T-SA: KAIROSNAME: C134
5C135 = 22U-10-T-SA: KAIROSNAME: C135
5C136 = 10U-10-X-S4-SS: KAIROSNAME: C136
5C137 = 0.1U-25-X-S4-TY: KAIROSNAME: C137
5C138 = 10U-10-X-S4-SS: KAIROSNAME: C138
5C139 = 22U-25-X-S8-MU: KAIROSNAME: C139
5C140 = 47U-16-T-SC: KAIROSNAME: C140
5C141 = 10U-16-T-SA: KAIROSNAME: C141
5C142 = 22U-25-X-S8-MU: KAIROSNAME: C142
5J5 = HDR-1X1-M: KAIROSNAME: J5
5J6 = HDR-2X1-M: KAIROSNAME: J6
5J7 = HDR-2X1-M: KAIROSNAME: J7
5J8 = HDR-2X1-M: KAIROSNAME: J8
5J9 = HDR-2X1-M: KAIROSNAME: J9
5K20 = CU_UA2-12NJ-A-V2: KAIROSNAME: K20
5K21 = CU_UA2-12NJ-A-V2: KAIROSNAME: K21
5K22 = CU_UA2-12NJ-A-V2: KAIROSNAME: K22
5K23 = CU_UA2-12NJ-A-V2: KAIROSNAME: K23
5K25 = CU_UA2-12NJ-A-V2: KAIROSNAME: K25
5K26 = CU_UA2-12NJ-A-V2: KAIROSNAME: K26
5K28 5K30-5K32 = CU_UA2-12NJ-A-V2: KAIROSNAME: K28
5K29 = CU_UA2-12NJ-A-V2: KAIROSNAME: K29
5L1 = L2.2U-1.15A-S2.0X1.6-TDK: KAIROSNAME: L1
5L3 = L2.2U-1.15A-S2.0X1.6-TDK: KAIROSNAME: L3
5L4 = L2.2U-1.15A-S2.0X1.6-TDK: KAIROSNAME: L4
5R48 = 0-5-S4: KAIROSNAME: R48
5R49 = 0-5-S4: KAIROSNAME: R49
5R50 = 0-5-S4: KAIROSNAME: R50
5R51 = 0-5-S4: KAIROSNAME: R51
5R53 = 0-5-S4: KAIROSNAME: R53
5R54 = 0-5-S4: KAIROSNAME: R54
5R55 = 0-5-S4: KAIROSNAME: R55
5R71-5R73 = 2-5-D-2
5R76-5R79 5R81-5R83 = 0-5-S4
5ST3 5ST13-5ST15 = SHORT: KAIROSNAME: ST3
5ST4 = SHORT: KAIROSNAME: ST4
5ST5 5ST16-5ST19 = SHORT: KAIROSNAME: ST5
5ST8 = SHORT: KAIROSNAME: ST8
5ST11 = SHORT: KAIROSNAME: ST11
5ST12 = SHORT: KAIROSNAME: ST12
S5_1V3 = TP03-D: KAIROSNAME: S0_TP_VD3
S5_GND1 = TP03-D: KAIROSNAME: S0_GND1
S5_GND2 = TP03-D: KAIROSNAME: S0_GND2
S5_GND3 = TP03-D: KAIROSNAME: S0_GND3
S5_GND4 = TP03-D: KAIROSNAME: S0_GND4
S5_VD33_ALL1 = TP03-D: KAIROSNAME: S0_VD33_ALL1
S5_VDD09 = TP03-D: KAIROSNAME: S0_VDD09
S5_VDD18_A = TP03-D: KAIROSNAME: S0_VDD18_A
S5_VDD18_D = TP03-D: KAIROSNAME: S0_VDD18_D

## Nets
AGND: 5BD34.2 5BD35.2 5C1.1 5C3.2 5C4.1 5C5.2 5C8.2 5C9.1 5C10.2 5C11.1 5C12.2 5C15.2 5C16.1 5C19.2 5D1.2(CATHODE_D2) 5D2.2(CATHODE_D2) 5D3.2(CATHODE_D2) 5SMP1.G1 5SMP1.G2 5SMP1.G3 5SMP1.G4 5SMP1.G5 5SMP1.G6 5SMP1.G7 5SMP1.G8 5SMP1.G9 5SMP2.G1 5SMP2.G2 5SMP2.G3 5SMP2.G4 5SMP2.G5 5SMP2.G6 5SMP2.G7 5SMP2.G8 5SMP2.G9 5SMP3.G1 5SMP3.G2 5SMP3.G3 5SMP3.G4 5SMP3.G5 5SMP3.G6 5SMP3.G7 5SMP3.G8 5SMP3.G9 5U1.2(GND) 5U2.2(GND) ; also on sheet 2 5 8 11 14 20 23
DGND: 5BD34.1 5BD35.1 5C17.1 5C18.1 5C20.2 5C21.2 5C22.2 5C23.1 5C24.2 5C25.1 5C38.1 5C39.2 5C40.1 5C41.2 5C44.2 5C45.2 5C46.2 5C47.2 5C48.2 5C49.2 5C52.2 5C53.2 5C54.2 5C55.2 5C56.2 5C57.2 5C58.2 5C59.2 5C60.2 5C61.2 5C62.2 5C63.2 5C64.2 5C65.2 5C66.2 5C67.2 5C68.2 5C69.2 5C70.2 5C71.2 5C72.2 5C73.2 5C74.2 5C75.2 5C76.2 5C77.2 5C78.2 5C79.2 5C83.2 5C84.2 5C85.2 5C88.2 5C89.2 5C90.2 5C91.2 5C92.2 5C93.2 5C94.2 5C95.2 5C96.2 5C97.2 5C98.2 5C99.2 5C100.2 5C101.2 5C102.2 5C105.2 5C106.2 5C107.2 5C108.2 5C109.2 5C110.2 5C111.2 5C112.2 5C113.1 5C116.2 5C117.2 5C118.2 5C119.2 5C120.2 5C121.2 5C122.2 5C123.2 5C124.2 5C125.2 5C126.2 5C127.2 5C128.2 5C129.2 5C130.2 5C131.2 5C132.2 5C133.2 5C134.2 5C135.2 5C136.2 5C137.2 5C138.2 5C139.2 5C140.2 5C141.2 5C142.2 5C143.1 5C144.1 5C145.1 5C146.1 5C147.1 5C148.1 5C149.1 5C150.1 5C152.2 5C153.2 5J1.2 5J2.2 5J3.2 5J4.8 5R18.1 5R22.2 5R23.2 5R25.2 5R26.2 5R33.1 5R42.2 5R43.2 5R49.2 5R51.2 5R54.2 5R62.2 5R71.2 5R72.2 5R73.2 5ST5.2 5ST16.2 5ST17.2 5ST18.2 5ST19.2 5U3.4(GND) 5Y1.2 5Y1.4 S5_GND1.1(TP) S5_GND2.1(TP) S5_GND3.1(TP) S5_GND4.1(TP) SITE5.4(GND_SPS_DCORE) SITE5.30(GND) SITE5.74(GND_SPS_MEM) SITE5.99(GND_SPS_AUD) SITE5.EP(EPAD) SITE5.G1 SITE5.G2 SITE5.G3 SITE5.G4 SITE5.G5 SITE5.G6 SITE5.G7 SITE5.G8 SITE5.G9 SITE5.G10 SITE5.G11 SITE5.G12 SITE5.G13 SITE5.G14 SITE5.G15 SITE5.G16 SITE5.G17 SITE5.G18 SITE5.G19 SITE5.G20 SITE5.G21 SITE5.G22 SITE5.G23 SITE5.G24 SITE5.G25 SITE5.G26 SITE5.G27 SITE5.G28 SITE5.G29 SITE5.G30 SITE5.G31 SITE5.G32 SITE5.G33 ; also on sheet 2 3 4 5 6 7 8 9 10 11 12 13 14 15 16 20 21 22 23 24 25 26 27 29 30 32 34 37 39
S5_1_AOUT_LN: 5K10.4 5R45.1 5R67.1 5R68.1
S5_1_AOUT_LP: 5K10.5 5R69.1 5R70.1 5R75.1
S5_1_AOUT_RN: 5K14.4 5R47.1 5R63.1 5R64.1
S5_1_AOUT_RP: 5K14.5 5R65.1 5R66.1 5R74.1
S5_1_SPI_CLK: 5R15.1 5U3.6(SCLK)
S5_1_SPI_CS: 5R10.2 5U3.1(CS#)
S5_1_SPI_DATA0: 5R17.1 5U3.5(SI/SIO0)
S5_1_SPI_DATA1: 5R11.2 5U3.2(SO/SIO1)
S5_1_SPI_DATA2: 5R14.2 5R16.2 5R18.2 5U3.3(WP#/SIO2)
S5_1_SPI_DATA3: 5R12.1 5R13.1 5U3.7(RST#/SIO3)
S5_1_VDD09: 5BD1.1 5BD2.1 5BD37.1 5C60.1 5R48.2 5R76.1 5R77.1 5R78.1 5R79.1 5ST13.2
S5_1_VDD18_A: 5K26.2 5K26.5 5R50.1 S5_1V3.1(TP)
S5_1_VDD18_D: 5C113.2 5R53.2 5R81.1 5R82.1 5R83.1 5ST15.1
S5_2_AOUT_LN: 5K12.4 5R68.2
S5_2_AOUT_LP: 5K12.5 5R69.2
S5_2_AOUT_RN: 5K15.4 5R64.2
S5_2_AOUT_RP: 5K15.5 5R65.2
S5_2_VDD18_A: 5BD16.1 5BD17.1 5BD19.1 5BD20.1 5C89.1 5R50.2
S5_ATX_VD0V9: 5C65.1 5C66.1 5K21.6 5ST3.2 ; also on sheet 27
S5_ATX_VD1V8: 5J7.1 5J8.1 5J9.1 ; also on sheet 27
S5_ATX_VD33: 5BD33.1 5C131.1 5C132.1 5C133.1 5C134.1 5C135.1 5J6.2 ; also on sheet 27
S5_AVCC_DRV: 5C75.1 5C110.1 5R55.2 5ST14.1 SITE5.53(AVCC_DRV)
S5_CHIP_EN_1: 5R34.2 5SW5.1
S5_DPS_F001: 5C120.1 5C121.1 5J9.2 5K29.6 5ST11.2
S5_DPS_F002: 5C92.1 5C93.1 5C94.1 5C95.1 5J8.2 5K26.6 5ST8.2
S5_DPS_F004: 5C140.1 5C141.1 5J7.2 5K20.6 5ST12.2
S5_DPS_F006: 5C68.1 5C69.1 5C70.1 5C71.1 5C72.1 5K23.3 5K23.6 5ST4.2 S5_VD33_ALL1.1(TP)
S5_DPS_GS001: 5ST19.1
S5_DPS_GS002: 5ST18.1
S5_DPS_GS003-1: 5ST16.1
S5_DPS_GS004: 5ST17.1
S5_DPS_GS006: 5ST5.1
S5_DPS_S001: 5ST11.1
S5_DPS_S002: 5ST8.1
S5_DPS_S003-1: 5ST3.1
S5_DPS_S004: 5ST12.1
S5_DPS_S006: 5ST4.1
S5_HSDM: 5K5.8 SITE5.79(HSDM)
S5_HSDP: 5K5.2 SITE5.78(HSDP)
S5_LPC_001: 5K36.7
S5_LPC_002: 5K36.2
S5_LPC_003: 5K11.2
S5_LPC_005: 5K14.2
S5_LPC_006: 5K18.4
S5_LPC_007: 5K1.4
S5_LPC_008: 5K35.2
S5_LPC_010: 5K34.7
S5_LPC_013+: 5K5.3 5K7.2
S5_LPC_013-: 5K5.7 5K7.8
S5_LPC_016: 5K2.5
S5_LPC_017: 5K35.7
S5_LPC_019: 5K12.2
S5_LPC_021: 5K1.5
S5_LPC_022: 5K15.2
S5_LPC_023: 5K3.4
S5_LPC_024: 5J4.2 5R35.1 SITE5.69(UART2_TXD/TEST_MODE_SEL/DMIC0_CLK/GPIOF_1/PB[22])
S5_LPC_025: 5J4.1 5R34.1 SITE5.71(CHIP_EN)
S5_LPC_026: 5K2.4
S5_LPC_027: 5K10.2
S5_LPC_028: 5K10.7
S5_LPC_029: 5K13.7
S5_LPC_030: 5K16.2
S5_LPC_032: 5K15.7
S5_LPC_033: 5K14.7
S5_LPC_034: 5K18.5
S5_LPC_035: 5K12.7
S5_LPC_036: 5K34.2
S5_LPC_038: 5K13.2
S5_LPC_039: 5K3.5
S5_LPC_040: 5K11.7
S5_LPC_041: 5J4.3 5R36.1 SITE5.68(UART2_RXD/BOOT_SEL/DMIC0_DATA/GPIOF_0/PB[21])
S5_LPC_042: 5C18.2 SITE5.50(MIC_BIAS2/GPIOC_13/PA[31])
S5_LPC_044: 5J4.5 5R39.1 SITE5.58(I2S3_DOUT1/DMIC_DATA2/ICFG1/GPIOD_4/PB[11])
S5_LPC_045: 5K39.3
S5_LPC_046: SITE5.67(I2S2_DIN3/I2S3_DOUT3/SPK_CLK/SPI0_CS/GPIOE_6/PB[20])
S5_LPC_047: 5J4.7 5R41.1 SITE5.18(GPIOB_7/PA[16]/ICFG3/SPI0_CS/UART0_RTS/HP_I2C2_SCL/ANT_SEL_N)
S5_LPC_048: 5K6.4
S5_LPC_049: SITE5.8(GPIOA_5/PA[5]/TOUCH5/ADC5/UART1_TXD/SPI1_MOSI/PWM4)
S5_LPC_050: SITE5.7(GPIOA_4/PA[4]/TOUCH4/ADC4/UART1_RXD/SPI1_MISO/PWM3/HP_I2C1_SCL)
S5_LPC_051: 5C17.2 SITE5.49(MIC_BIAS1/GPIOC_12/PA[30])
S5_LPC_052: 5C21.1 SITE5.48(AVCC)
S5_LPC_053: 5J4.4 5R37.1 SITE5.57(I2S3_DOUT0/DMIC_DATA1/ICFG0/BT_LOG/GPIOD_3/PB[10])
S5_LPC_054: 5K6.5
S5_LPC_055: SITE5.10(VBAT_MEAS)
S5_LPC_057: 5K9.4
S5_LPC_058: 5J4.6 5R40.1 SITE5.17(GPIOB_6/PA[15]/ICFG2/SPI0_CLK/UART0_CTS/HP_I2C2_SDA/ANT_SEL_P)
S5_LPC_059: 5K39.6
S5_LPC_060: SITE5.66(I2S2_DIN2/I2S3_DOUT2/SPK_DATA/SPI0_CK/GPIOE_5/PB[19])
S5_LPC_A_015: 5K8.4
S5_LPC_A_020: 5K8.5
S5_LPC_B_031: 5K4.4
S5_LPC_B_037: 5K4.5
S5_LX_AUD: 5K20.3 SITE5.100(LX_AUD)
S5_LX_AUD_CH_1: 5K20.4 ; also on sheet 16
S5_LX_AUD_CH_2: 5ST14.2 ; also on sheet 16
S5_LX_DCORE: 5K21.3 SITE5.3(LX_DCORE)
S5_LX_DCORE_CH: 5K21.4 ; also on sheet 16
S5_LX_MEM: 5K29.3 SITE5.75(LX_MEM)
S5_LX_MEM_CH_1: 5K29.4 ; also on sheet 16
S5_LX_MEM_CH_2: 5ST15.2 ; also on sheet 16
S5_MIPITX_CKN: 5K36.6 SITE5.82(MIPITX_CKN)
S5_MIPITX_CKP: 5K36.3 SITE5.83(MIPITX_CKP)
S5_MIPITX_DATAN_0: 5K34.6 SITE5.85(MIPITX_DATAN_0)
S5_MIPITX_DATAN_1: 5K35.6 SITE5.80(MIPITX_DATAN_1)
S5_MIPITX_DATAP_0: 5K34.3 SITE5.86(MIPITX_DATAP_0)
S5_MIPITX_DATAP_1: 5K35.3 SITE5.81(MIPITX_DATAP_1)
S5_PA2: 5K18.3 SITE5.5(GPIOA_2/PA[2]/TOUCH2/ADC2/UART0_RXD/SPI1_CS)
S5_PA3: 5K18.6 SITE5.6(GPIOA_3/PA[3]/TOUCH3/ADC3/UART0_TXD/SPI1_CLK/LEDC/HP_I2C1_SDA)
S5_PA9_CH: 5K39.2 SITE5.12(GPIOB_0/PA[9])
S5_PA10_CH: 5K39.7 SITE5.13(GPIOB_1/PA[10])
S5_PA13: 5K6.3 SITE5.15(GPIOB_4/PA[13]/SWD_DATA/SPI0_MOSI/UART0_RXD/HP_I2C1_SDA)
S5_PA13_UART_RX: 5K6.2 5R27.1
S5_PA13_UART_RX_1: 5J2.3 5R27.2
S5_PA14: 5K6.6 SITE5.16(GPIOB_5/PA[14]/SWD_CLK/SPI0_MISO/UART0_TXD/HP_I2C1_SCL)
S5_PA14_UART_TX: 5K6.7 5R28.1
S5_PA14_UART_TX_1: 5J2.4 5R28.2
S5_PA15_1: 5R40.2 5SW5.6
S5_PA16_1: 5R41.2 5SW5.7
S5_PA20: 5K15.6 SITE5.45(MIC1_P/GPIOC_2/PA[20])
S5_PA21: 5K15.3 SITE5.46(MIC1_N/GPIOC_3/PA[21])
S5_PA22: 5K11.6 SITE5.43(MIC2_P/GPIOC_4/PA[22])
S5_PA23: 5K11.3 SITE5.44(MIC2_N/GPIOC_5/PA[23])
S5_PA24: 5K12.6 SITE5.41(MIC3_P/I2C_SDA/GPIOC_6/PA[24])
S5_PA25: 5K12.3 SITE5.42(MIC3_N/I2C_SCL/GPIOC_7/PA[25])
S5_PA28: 5K13.6 SITE5.39(MIC5_P/ANT_SEL_P/GPIOC_10/PA[28])
S5_PA29: 5K13.3 SITE5.40(MIC5_N/ANT_SEL_N/GPIOC_11/PA[29])
S5_PB3: 5K10.6 SITE5.52(AOUT_LP/GPIOC_17/PB[3])
S5_PB3_AOUT_LP_2: 5K13.5 5R70.2
S5_PB4: 5K10.3 SITE5.51(AOUT_LN/GPIOC_18/PB[4])
S5_PB4_AOUT_LN_2: 5K13.4 5R67.2
S5_PB5: 5K14.6 SITE5.54(AOUT_RP/GPIOC_19/PB[5])
S5_PB5_AOUT_RP_2: 5K11.5 5R66.2
S5_PB6: 5K14.3 SITE5.55(AOUT_RN/GPIOC_20/PB[6])
S5_PB6_AOUT_RN_2: 5K11.4 5R63.2
S5_PB10_1: 5R37.2 5SW5.4
S5_PB11_1: 5R39.2 5SW5.5
S5_PB21_1: 5R36.2 5SW5.3
S5_PB22_1: 5R35.2 5SW5.2
S5_PB23: 5C144.2 5K4.3 5R57.1 SITE5.72(UART_LOG_RXD/OTP_BYPASS/GPIOF_2/PB[23])
S5_PB23_1: 5R57.2 5SW6.1
S5_PB23_SICK: 5K4.2 5R20.1
S5_PB23_SICK_1: 5J1.3 5R20.2
S5_PB24: 5C143.2 5K4.6 5R58.1 SITE5.73(UART_LOG_TXD/UART_DOWNLOAD/GPIOF_3/PB[24])
S5_PB24_1: 5R58.2 5SW6.2
S5_PB24_SIDD: 5K4.7 5R21.1
S5_PB24_SIDD_1: 5J1.4 5R21.2
S5_PB25: 5K8.3 5R59.1 SITE5.96(SPI0_CLK/SWD_CLK/SD_D2/ICFG2/GPIOG_0/PB[25])
S5_PB25_1: 5R59.2 5SW6.3
S5_PB25_I2C_SCL: 5K8.2 5R31.1
S5_PB25_I2C_SCL_1: 5J3.3 5R31.2
S5_PB26: 5K8.6 5R60.1 SITE5.97(SPI0_CS/SWD_DATA/SD_D3/ICFG3/GPIOG_1/PB[26])
S5_PB26_1: 5R60.2 5SW6.4
S5_PB26_I2C_SDA: 5K8.7 5R32.1
S5_PB26_I2C_SDA_1: 5J3.4 5R32.2
S5_RF_A: 5C13.1 5C14.1 5C15.1 5D3.1(CATHODE_D1) 5SMP3.1
S5_RF_G: 5C6.1 5C7.1 5C8.1 5D2.1(CATHODE_D1) 5SMP2.1
S5_RFIN_A: 5C16.2 5R9.1 SITE5.29(RFIN_A/GND_(<750um))
S5_RFIN_G: 5C9.2 5R5.1 SITE5.31(RFIN_G/GND)
S5_RFIO_A: 5C11.2 5R6.1 SITE5.28(RFIO_A__(<750um))
S5_RFIO_BT: 5C1.2 5R1.1 SITE5.37(RFIO_BT)
S5_RFIO_G: 5C4.2 5R2.1 SITE5.32(RFIO_G)
S5_RREF_MEM: 5K9.3 5R43.1 SITE5.60(RREF_MEM)
S5_SPI_CLK: 5K1.7 5R15.2
S5_SPI_CLK/PB28: 5K1.6 SITE5.90(SPI_FLASH_CLK/SD_CLK/GPIOG_3/PB[28])
S5_SPI_CS: 5K3.2 5R10.1
S5_SPI_CS/PC0: 5K3.3 SITE5.95(SPI_FLASH_CS/UART1_CTS/SD_CD/GPIOG_7/PC[0])
S5_SPI_D0/PB29: 5K1.3 SITE5.91(SPI_FLASH_DATA0/UART1_RXD/SD_D0/GPIOG_4/PB[29])
S5_SPI_D1/PB31: 5K3.6 SITE5.94(SPI_FLASH_DATA1/UART1_RTS/SD_WP/GPIOG_6/PB[31])
S5_SPI_D2/PB30: 5K2.6 SITE5.92(SPI_FLASH_DATA2/UART1_TXD/SD_D1/GPIOG_5/PB[30])
S5_SPI_D3/PB27: 5K2.3 SITE5.89(SPI_FLASH_DATA3/SD_CMD/GPIOG_2/PB[27])
S5_SPI_DATA0: 5K1.2 5R17.2
S5_SPI_DATA1: 5K3.7 5R11.1
S5_SPI_DATA2: 5K2.7 5R16.1
S5_SPI_DATA3: 5K2.2 5R13.2
S5_U1_VC1: 5K39.5 5U1.4(VCTL)
S5_U2_VC1: 5K39.4 5U2.4(VCTL)
S5_VA09_MIPI: 5BD37.2 5C152.1 SITE5.84(VA09_MIPI/VA09_CK/VA09_DA)
S5_VA09_PLL: 5BD1.2 5C44.1 SITE5.11(VA09_PLL/VD09_CORE0)
S5_VA09_USB: 5BD2.2 5C45.1 SITE5.77(VA09_USB)
S5_VA13_AFE: 5BD20.2 5C88.1 SITE5.19(VA13_AFE)
S5_VA13_SYN: 5BD16.2 5C78.1 SITE5.23(VR13_SYN)
S5_VA33_SYN: 5BD13.2 5C64.1 SITE5.24(VR33_SYN)
S5_VA33_XTAL: 5BD5.2 5C48.1 SITE5.20(VA33_XTAL)
S5_VD09_CORE1: 5C47.1 5R76.2 SITE5.56(VD09_CORE1/VD09MEM0)
S5_VD09_CORE2: 5C49.1 5R77.2 SITE5.64(VD09_CORE2/VD09_MEM1)
S5_VD09_CORE3: 5C54.1 5R78.2 SITE5.87(VD09_CORE3/VA09_PLL)
S5_VD09_CORE4: 5C58.1 5R79.2 SITE5.98(VD09_CORE4)
S5_VD13_FE: 5BD19.2 5C85.1 SITE5.36(VD13_FE)
S5_VD13_RF: 5BD17.2 5C79.1 SITE5.25(VD13_RF)
S5_VD33_ALL: 5BD3.1 5BD5.1 5BD7.1 5BD9.1 5BD11.1 5BD12.1 5BD13.1 5BD15.1 5BD18.1 5BD21.1 5BD22.1 5BD23.1 5BD28.1 5BD29.1 5BD30.1 5BD31.1 5BD32.1 5BD36.1 5C67.1 5C96.1 5C101.1 5C122.1 5C129.1 5J5.1 5J6.1 5K23.2 5K23.7
S5_VD33_CM_BT: 5BD21.2 5C90.1 5C91.1 SITE5.35(VD33_CM_BT)
S5_VD33_EX_FLASH: 5BD32.2 5C22.1 5C127.1 5C128.1 5R12.2 5R14.1 5U3.8(VCC)
S5_VD33_IO0: 5BD7.2 5C52.1 SITE5.9(VA33_PLL/VD33_IO0)
S5_VD33_IO2: 5BD9.2 5C56.1 SITE5.59(VD33_IO2/VD33_MEM)
S5_VD33_IO3: 5BD11.2 5C59.1 SITE5.70(VD33_IO3/VDD_IO4/VA33_USB)
S5_VD33_IO6: 5BD12.2 5C61.1 SITE5.88(VD33_IO6/VDD33_IO5/VD33_FLASH)
S5_VD33_SPS_AUD: 5BD30.2 5C123.1 5C124.1 SITE5.1(VD33_SPS_AUD)
S5_VD33_SPS_DCORE: 5BD28.2 5C111.1 5C112.1 SITE5.2(VD33_SPS_DCORE)
S5_VD33_SPS_MEM: 5BD31.2 5C125.1 5C126.1 SITE5.76(VD33_SPS_MEM)
S5_VD33PA_A: 5BD23.2 5C99.1 5C100.1 SITE5.27(VD33PA_A)
S5_VD33PA_BT: 5BD18.2 5C83.1 5C84.1 SITE5.38(VD33PA_BT)
S5_VD33PA_G: 5BD15.2 5C76.1 5C77.1 SITE5.33(VD33PA_G)
S5_VD33PAD_A: 5BD22.2 5C97.1 5C98.1 SITE5.26(VD33PAD_A)
S5_VD33PAD_G: 5BD36.2 5C73.1 5C74.1 SITE5.34(VD33PAD_G)
S5_VD1833_IO1: 5BD3.2 5C46.1 SITE5.14(VD1833_IO1)
S5_VD1833_SDIO: 5BD29.2 5C118.1 5C119.1 SITE5.93(VD1833_SDIO)
S5_VD_MEM0: 5C102.1 5R81.2 SITE5.61(VD_MEM0)
S5_VD_MEM1: 5C105.1 5R82.2 SITE5.62(VD_MEM1)
S5_VD_MEM2: 5C107.1 5R83.2 SITE5.65(VD_MEM2)
S5_VDD09: 5K22.2 5K22.5 5K31.4 5R48.1 S5_VDD09.1(TP)
S5_VDD09_CH: 5ST13.1 ; also on sheet 16
S5_VDD18_A: 5K25.2 5K25.5 5K26.3 5K32.4 5R55.1 S5_VDD18_A.1(TP)
S5_VDD18_D: 5K28.2 5K28.5 5K30.4 5R29.2 5R53.1 S5_VDD18_D.1(TP)
S5_VDD33: 5BD33.2 5C130.1 5R19.1 5R24.1 5R30.1 5R38.2 5R61.2 5U1.6(VDD) 5U2.6(VDD)
S5_VDD33_J1: 5J1.1 5R19.2
S5_VDD33_J2: 5J2.1 5R24.2
S5_VDD33_J3: 5J3.1 5R30.2
S5_VREF_DRAM: 5C153.1 5K16.3 SITE5.63(VREF_DRAM/NC(PSRAM))
S5_XI: 5C25.2 5Y1.1 SITE5.22(XI)
S5_XO: 5C23.2 5Y1.3 SITE5.21(XO)
S4567_CBIT_001: 5K7.9(V-) ; also on sheet 14 20 23
S4567_CBIT_003: 5K6.8(V-) ; also on sheet 14 20 23
S4567_CBIT_004: 5K2.8(V-) ; also on sheet 14 20 23
S4567_CBIT_005: 5K3.8(V-) ; also on sheet 14 20 23
S4567_CBIT_006: 5K35.8(V-) ; also on sheet 14 15 21 24
S4567_CBIT_008: 5K30.8(V-) ; also on sheet 14 16 22 25
S4567_CBIT_009: 5K32.8(V-) ; also on sheet 14 16 22 25
S4567_CBIT_010: 5K31.8(V-) ; also on sheet 14 16 22 25
S4567_CBIT_011: 5K29.8(V-) ; also on sheet 14 16 22 25
S4567_CBIT_012: 5K28.8(V-) ; also on sheet 14 16 22 25
S4567_CBIT_013: 5K8.8(V-) ; also on sheet 14 20 23
S4567_CBIT_014: 5K26.8(V-) ; also on sheet 14 16 22 25
S4567_CBIT_015: 5K34.8(V-) ; also on sheet 14 15 21 24
S4567_CBIT_016: 5K16.8(V-) ; also on sheet 14 20 23
S4567_CBIT_017: 5K21.8(V-) ; also on sheet 14 16 22 25
S4567_CBIT_018: 5K18.8(V-) ; also on sheet 14 15 21 24
S4567_CBIT_019: 5K22.8(V-) ; also on sheet 14 16 22 25
S4567_CBIT_020: 5K9.8(V-) ; also on sheet 14 20 23
S4567_CBIT_022: 5K19.8(V-) ; also on sheet 14 15 21 24
S4567_CBIT_023: 5K23.8(V-) ; also on sheet 14 16 22 25
S4567_CBIT_024: 5K20.8(V-) ; also on sheet 14 16 22 25
S4567_CBIT_025: 5K13.8(V-) ; also on sheet 14 15 21 24
S4567_CBIT_026: 5K14.8(V-) ; also on sheet 14 15 21 24
S4567_CBIT_027: 5K15.8(V-) ; also on sheet 14 15 21 24
S4567_CBIT_028: 5K25.8(V-) ; also on sheet 14 16 22 25
S4567_CBIT_029: 5K10.8(V-) ; also on sheet 14 15 21 24
S4567_CBIT_030: 5K11.8(V-) ; also on sheet 14 15 21 24
S4567_CBIT_031: 5K12.8(V-) ; also on sheet 14 15 21 24
S4567_CBIT_032: 5K39.8(V-) ; also on sheet 14 20 23
S4567_CBIT_033: 5K1.8(V-) ; also on sheet 14 20 23
S4567_CBIT_035: 5K5.9(V-) ; also on sheet 14 20 23
S4567_CBIT_036: 5K36.8(V-) ; also on sheet 14 15 21 24
S4567_CBIT_037: 5K4.8(V-) ; also on sheet 14 20 23
VP12: 5K1.1(V+) 5K2.1(V+) 5K3.1(V+) 5K4.1(V+) 5K5.1(V+) 5K6.1(V+) 5K7.1(V+) 5K8.1(V+) 5K9.1(V+) 5K10.1(V+) 5K11.1(V+) 5K12.1(V+) 5K13.1(V+) 5K14.1(V+) 5K15.1(V+) 5K16.1(V+) 5K18.1(V+) 5K19.1(V+) 5K20.1(V+) 5K21.1(V+) 5K22.1(V+) 5K23.1(V+) 5K25.1(V+) 5K26.1(V+) 5K28.1(V+) 5K29.1(V+) 5K30.1(V+) 5K31.1(V+) 5K32.1(V+) 5K34.1(V+) 5K35.1(V+) 5K36.1(V+) 5K39.1(V+) ; also on sheet 2 3 4 5 6 7 8 9 10 11 12 13 14 15 16 20 21 22 23 24 25 26 27 29 38
N27475373: 5C10.1 5R5.2 5U1.3(RF2)
N27475379: 5C7.2 5U1.5(ANT)
N27475382: 5R4.1 5U1.1(RF1)
N27475433: 5C6.2 5R3.2
N27475442: 5C19.1 5R9.2 5U2.1(RF1)
N27475449: 5C14.2 5U2.5(ANT)
N27475456: 5C12.1 5R6.2 5R7.1 5R8.2
N27475458: 5C13.2 5R7.2
N27475477: 5BD27.2 5C24.1 5K16.4
N27475487: 5K5.6 5R22.1
N27475489: 5K5.4 5R25.1
N27475492: 5R8.1 5U2.3(RF2)
N27475498: 5C5.1 5R2.2 5R3.1 5R4.2
N27475526: 5C2.1 5C3.1 5R1.2
N27475531: 5C2.2 5D1.1(CATHODE_D1) 5SMP1.1
N27475649: 5K7.6 5R23.1
N27475650: 5K7.4 5R26.1
N27475655: 5BD27.1 5R29.1 5R33.2
N27475782: 5C20.1 SITE5.47(VREF_AUDIO)
N27479381: 5K18.2 5K19.3
N27479382: 5K18.7 5K19.6
N27479385: 5C39.1 5K19.4
N27479386: 5C38.2 5K19.2
N27479389: 5C41.1 5K19.5
N27479390: 5C40.2 5K19.7
N27479421: 5R47.2 5R74.2
N27479503: 5R45.2 5R75.2
N27479519: 5C145.2 5K34.4
N27479520: 5C146.2 5K34.5
N27479527: 5C147.2 5K35.4
N27479528: 5C148.2 5K35.5
N27479531: 5C149.2 5K36.4
N27479532: 5C150.2 5K36.5
N27480619: 5K21.2 5L1.1
N27480649: 5K29.2 5L3.1
N27480650: 5C106.1 5C108.1 5C109.1 5K28.3 5L3.2
N27480661: 5K28.4 5R54.1
N27480665: 5C116.1 5C117.1 5K28.6 5K29.5
N27480688: 5C53.1 5C55.1 5C57.1 5K22.3 5L1.2
N27480700: 5K22.4 5R49.1
N27480704: 5C62.1 5C63.1 5K21.5 5K22.6
N27480819: 5K20.2 5L4.1
N27480820: 5C136.1 5C137.1 5C138.1 5K25.3 5L4.2
N27480831: 5K25.4 5R51.1
N27480833: 5C139.1 5C142.1 5K20.5 5K25.6
N27480939: 5K30.3 5R71.1
N27480941: 5K31.3 5R72.1
N27480943: 5K32.3 5R73.1
N27685777: 5R61.1 5SW6.6
N27685781: 5R62.1 5SW6.5
N27685861: 5R38.1 5SW5.10
N27685865: 5R42.1 5SW5.9

Not connected (* = marked no-connect by the designer): 5K7 3* 7*; 5K9 2* 5* 6* 7*; 5K16 5* 6* 7*; 5K20 7*; 5K21 7*; 5K22 7*; 5K23 4* 5*; 5K25 7*; 5K26 4* 7*; 5K28 7*; 5K29 7*; 5K30 2* 5* 6* 7*; 5K31 2* 5* 6* 7*; 5K32 2* 5* 6* 7*; 5SW5 8*; SITE5 GH1* GH2* GH3* GH4* NUT1* NUT2* NUT3* NUT4*

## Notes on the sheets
sheet 17
- WIFI/BT_RF
- place by Z-shape
- R3 and R4 Share PAD,
  Default R3
- C6 and C7 Share PAD,
  Default C6
- place by Z-shape
- place by Z-shape
- R7 and R8 Share PAD,
  Default R7
- C13 and C14 Share PAD,
  Default C13
- place by Z-shape
- place by Z-shape
- GND Shielding
- FLASH
- RF SW Channel  and PA9.10 share one Channel
- GND Shielding
- Mark On Board
- Debug
- GND Shielding
- 1.S0_VDD33
- 2.GND
- 3.S0_SICK
- DSSC
- 4.S0_SIDD
- SIC
- USB
- GND Shielding
- Mark On Board
- Debug
- 1.S0_VDD33
- 2.GND
- 3.S0_UART_RX
- 4.S0_UART_TX
- UART
- DIFF 90ohm
- DIFF 90ohm
- Mark On Board
- Debug
- XTAL
- VREF_DRAM
- 1.S0_VDD33
- GND Shielding
- 2.GND
- Close To DUT
- 3.S0_I2C_SCL
- DSSC
- 4.S0_I2C_SDA
- BT_I2C
- GND Shielding
- Mark On Board
- 1.S0_CHIP_EN
- 2.S0_PB22_TEST_MODE_SEL
- 3.S0_PB21_BOOT_SEL_FLASH
- 4.S0_PB10/ICFG0
- 5.S0_PB11/ICFG1
- 6.S0_PA15/ICFG2
- 7.S0_PA16/ICFG3
- 8.NC
- RREF
- Close to Relay
- Close To DUT
sheet 18
- AUDIO ADC Test
- MIPI Test
- GND Shielding
- GND Shielding
- CAP TOUCH Test
- GND Shielding
sheet 19
- CLOSE TO DUT
- POWER_VD09
- POWER_VD1833
- CLOSE TO DUT
- 110mA
- 5mA
- 33mA
- C48 TOP
- 20mA
- 102mA
- 35mA
- 105mA
- 35mA
- 112mA
- 25mA
- 50mA
- Mark On Board : S0_VDD09
- C58 TOP
- 30mA
- 50mA
- 10mA
- C64 TOP
- 200mA
- CLOSE TO DUT
- 200mA
- POWER_VD18_AUD
- CLOSE TO DUT
- Mark On Board : S0_VDD18_A
- 200mA
- 100mA
- C75 TOP
- 50mA
- Mark On Board : S0_VDD33
- CLOSE TO DUT
- CLOSE TO DUT
- 45mA
- 60mA
- C78 TOP
- 80mA
- C79 TOP
- 45mA
- C97,C98 TOP
- 300mA
- 25mA
- C88 TOP
- C99,C100 TOP
- POWER_VD18_DDR
- CLOSE TO DUT
- CLOSE TO DUT
- 155mA
- 62mA
- C111,C112 TOP
- 62mA
- 30mA
- 62mA
- Mark On Board : S0_VDD18_D
- C107 TOP
- 107mA
- C123,C124 TOP
- 160mA
- C125,C126 TOP
- 50mA
- Calibration Loading SCH
